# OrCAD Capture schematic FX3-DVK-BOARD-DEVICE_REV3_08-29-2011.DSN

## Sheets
1 PAGE07 : CLOCK SIGNALS: size B; title: FX3 DVK DEVICE BOARD; rev: 3.0; note: 630-60013-01 REV03
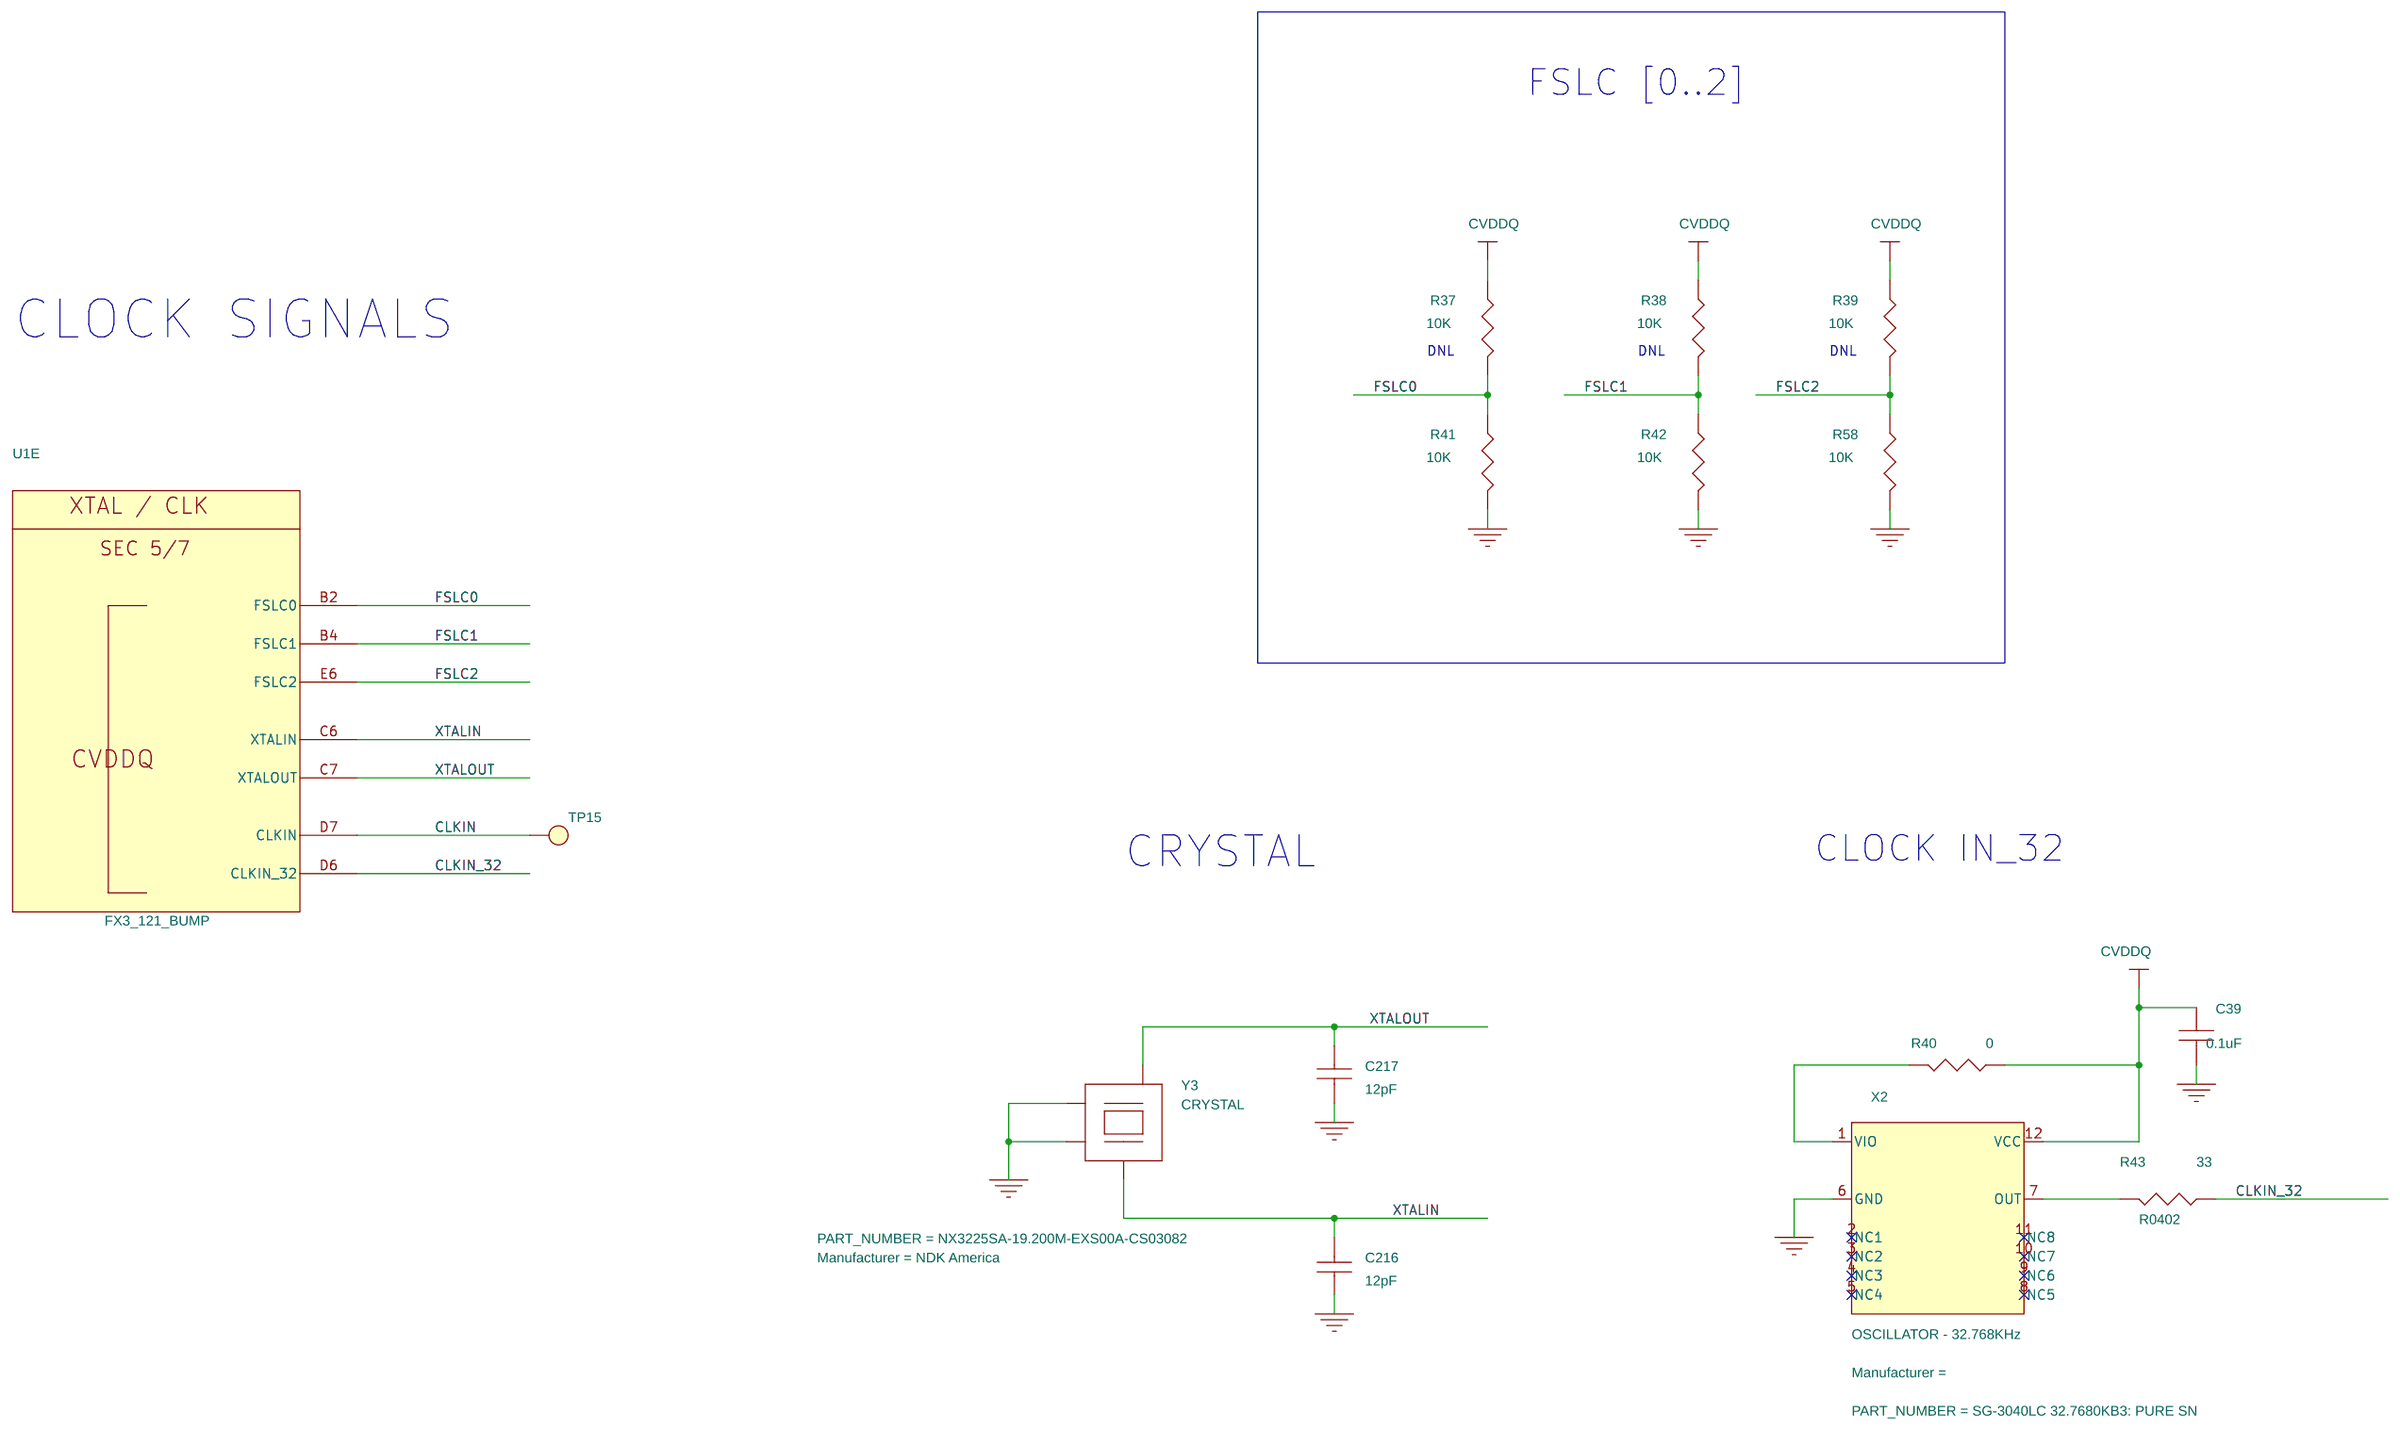
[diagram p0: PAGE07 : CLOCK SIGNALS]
2 PAGE14 : Power LED: size B
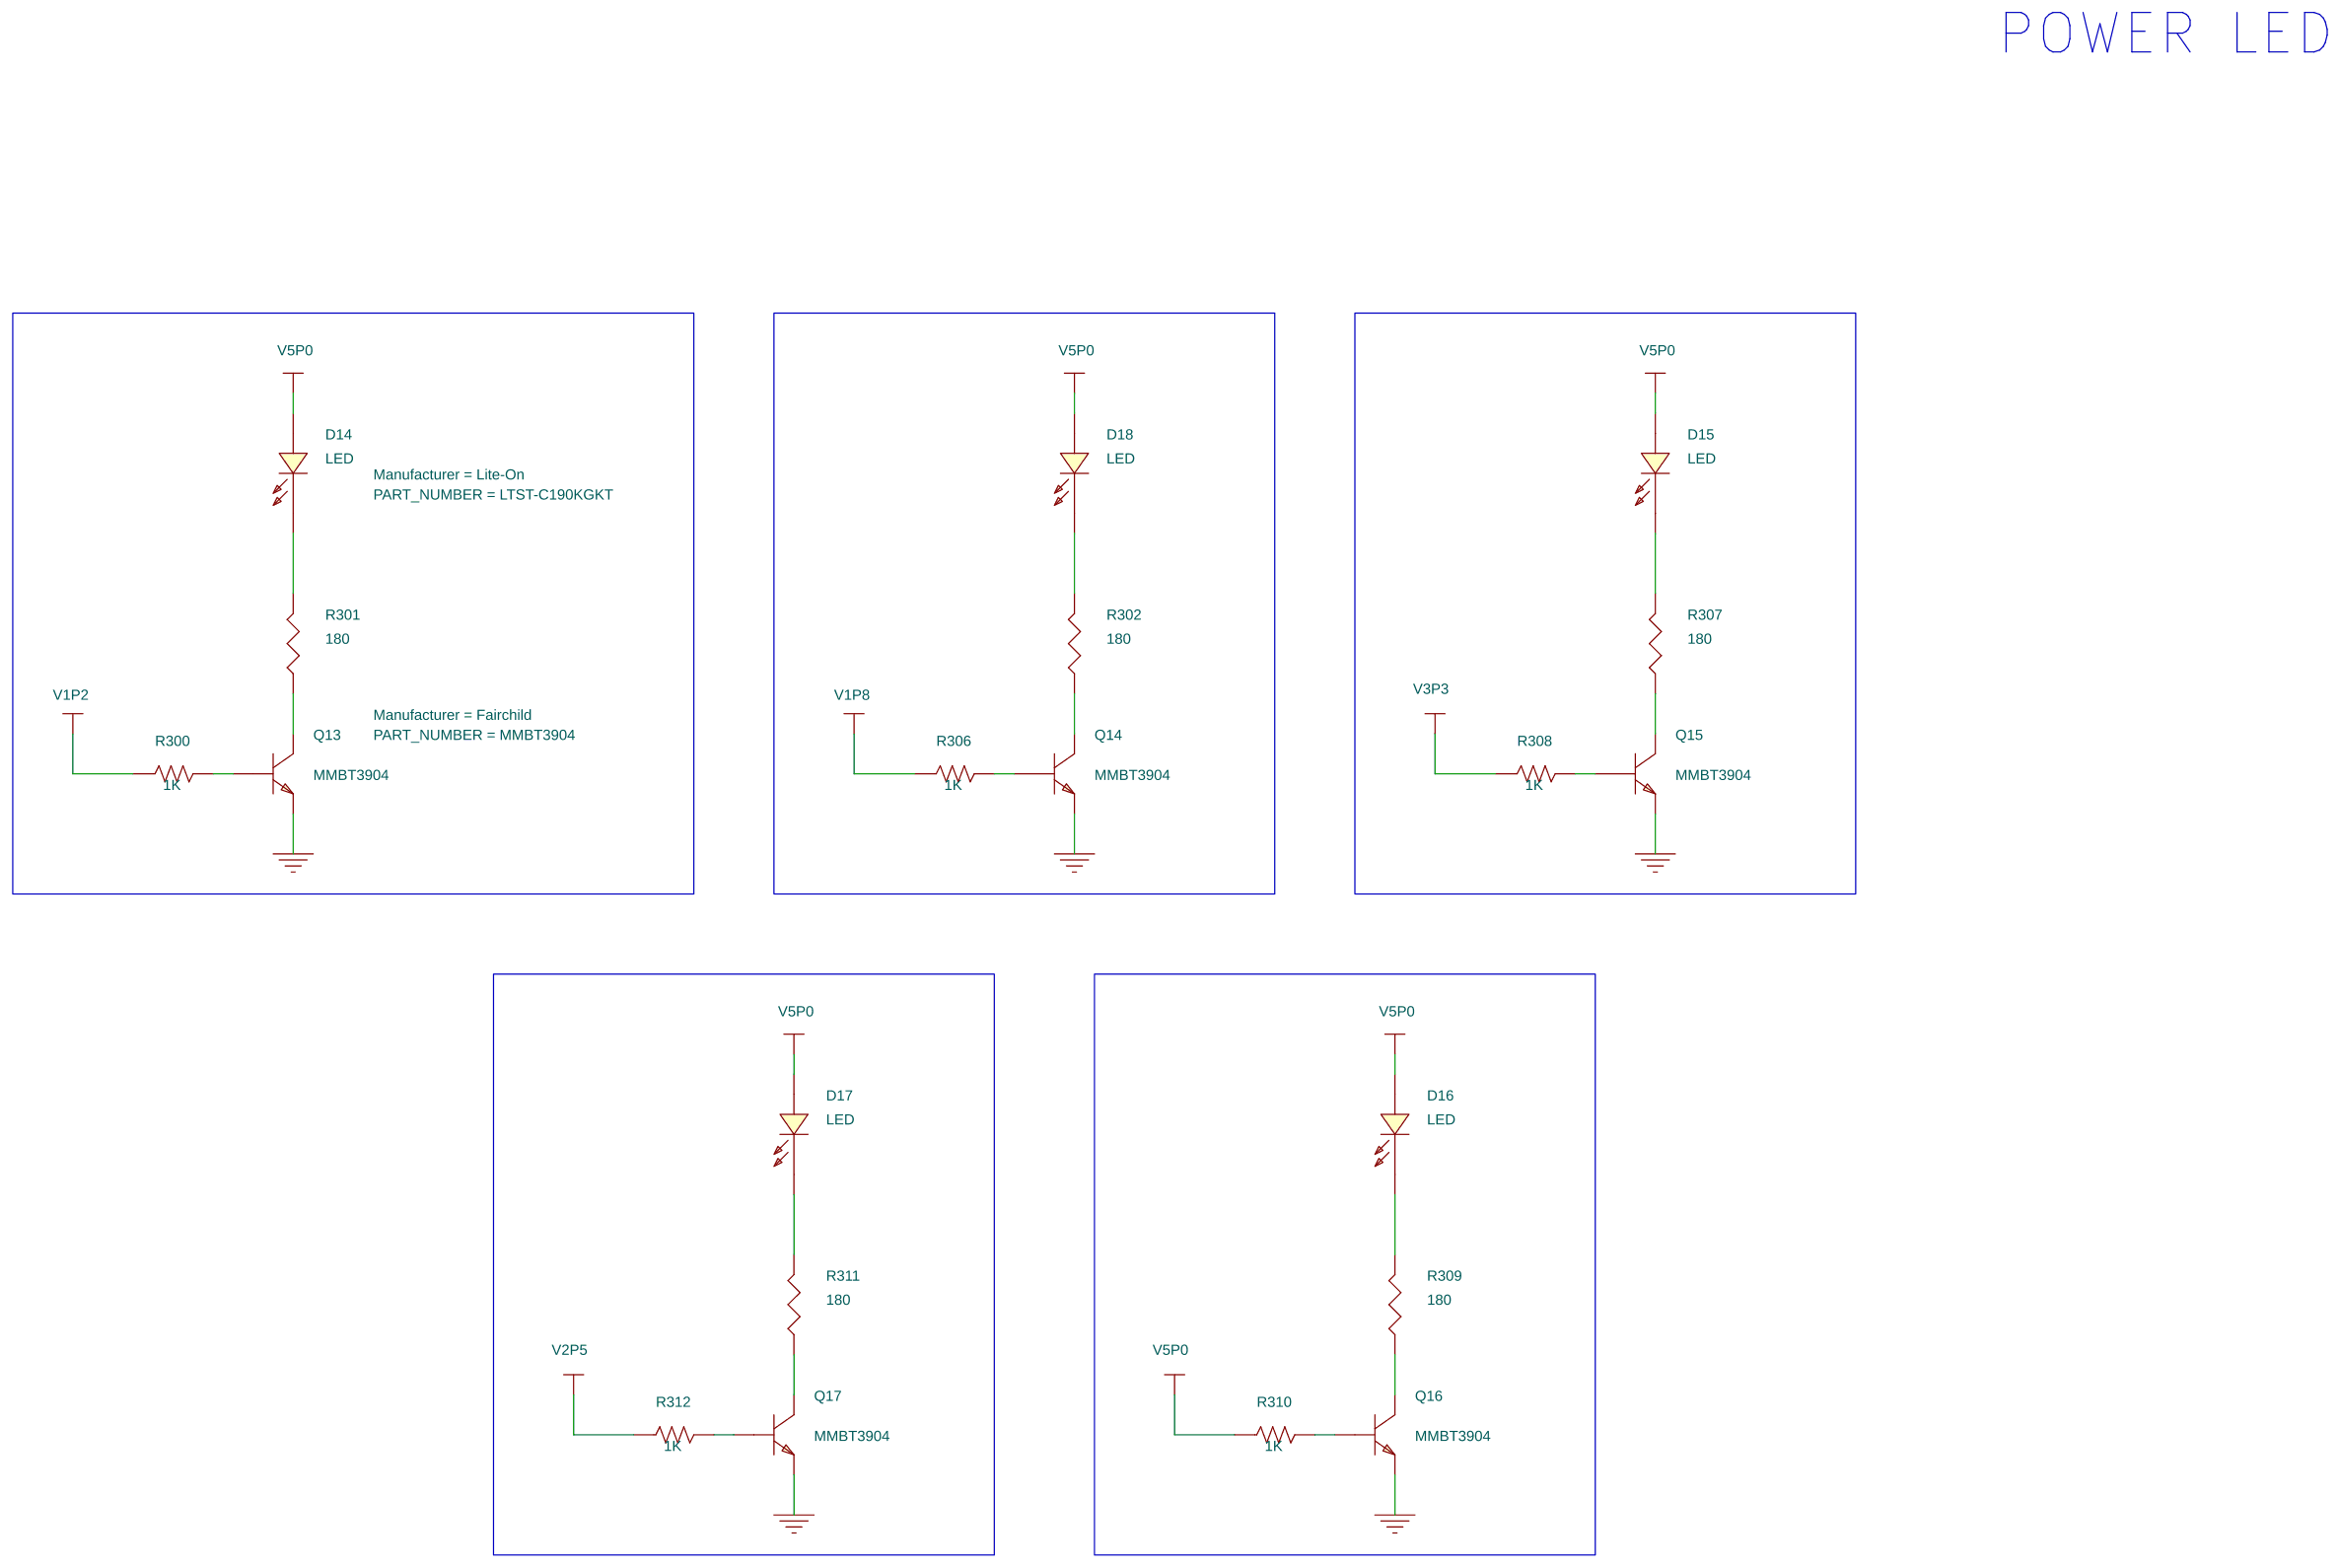
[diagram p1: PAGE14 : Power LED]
3 PAGE10 : FX3 POWER: size B
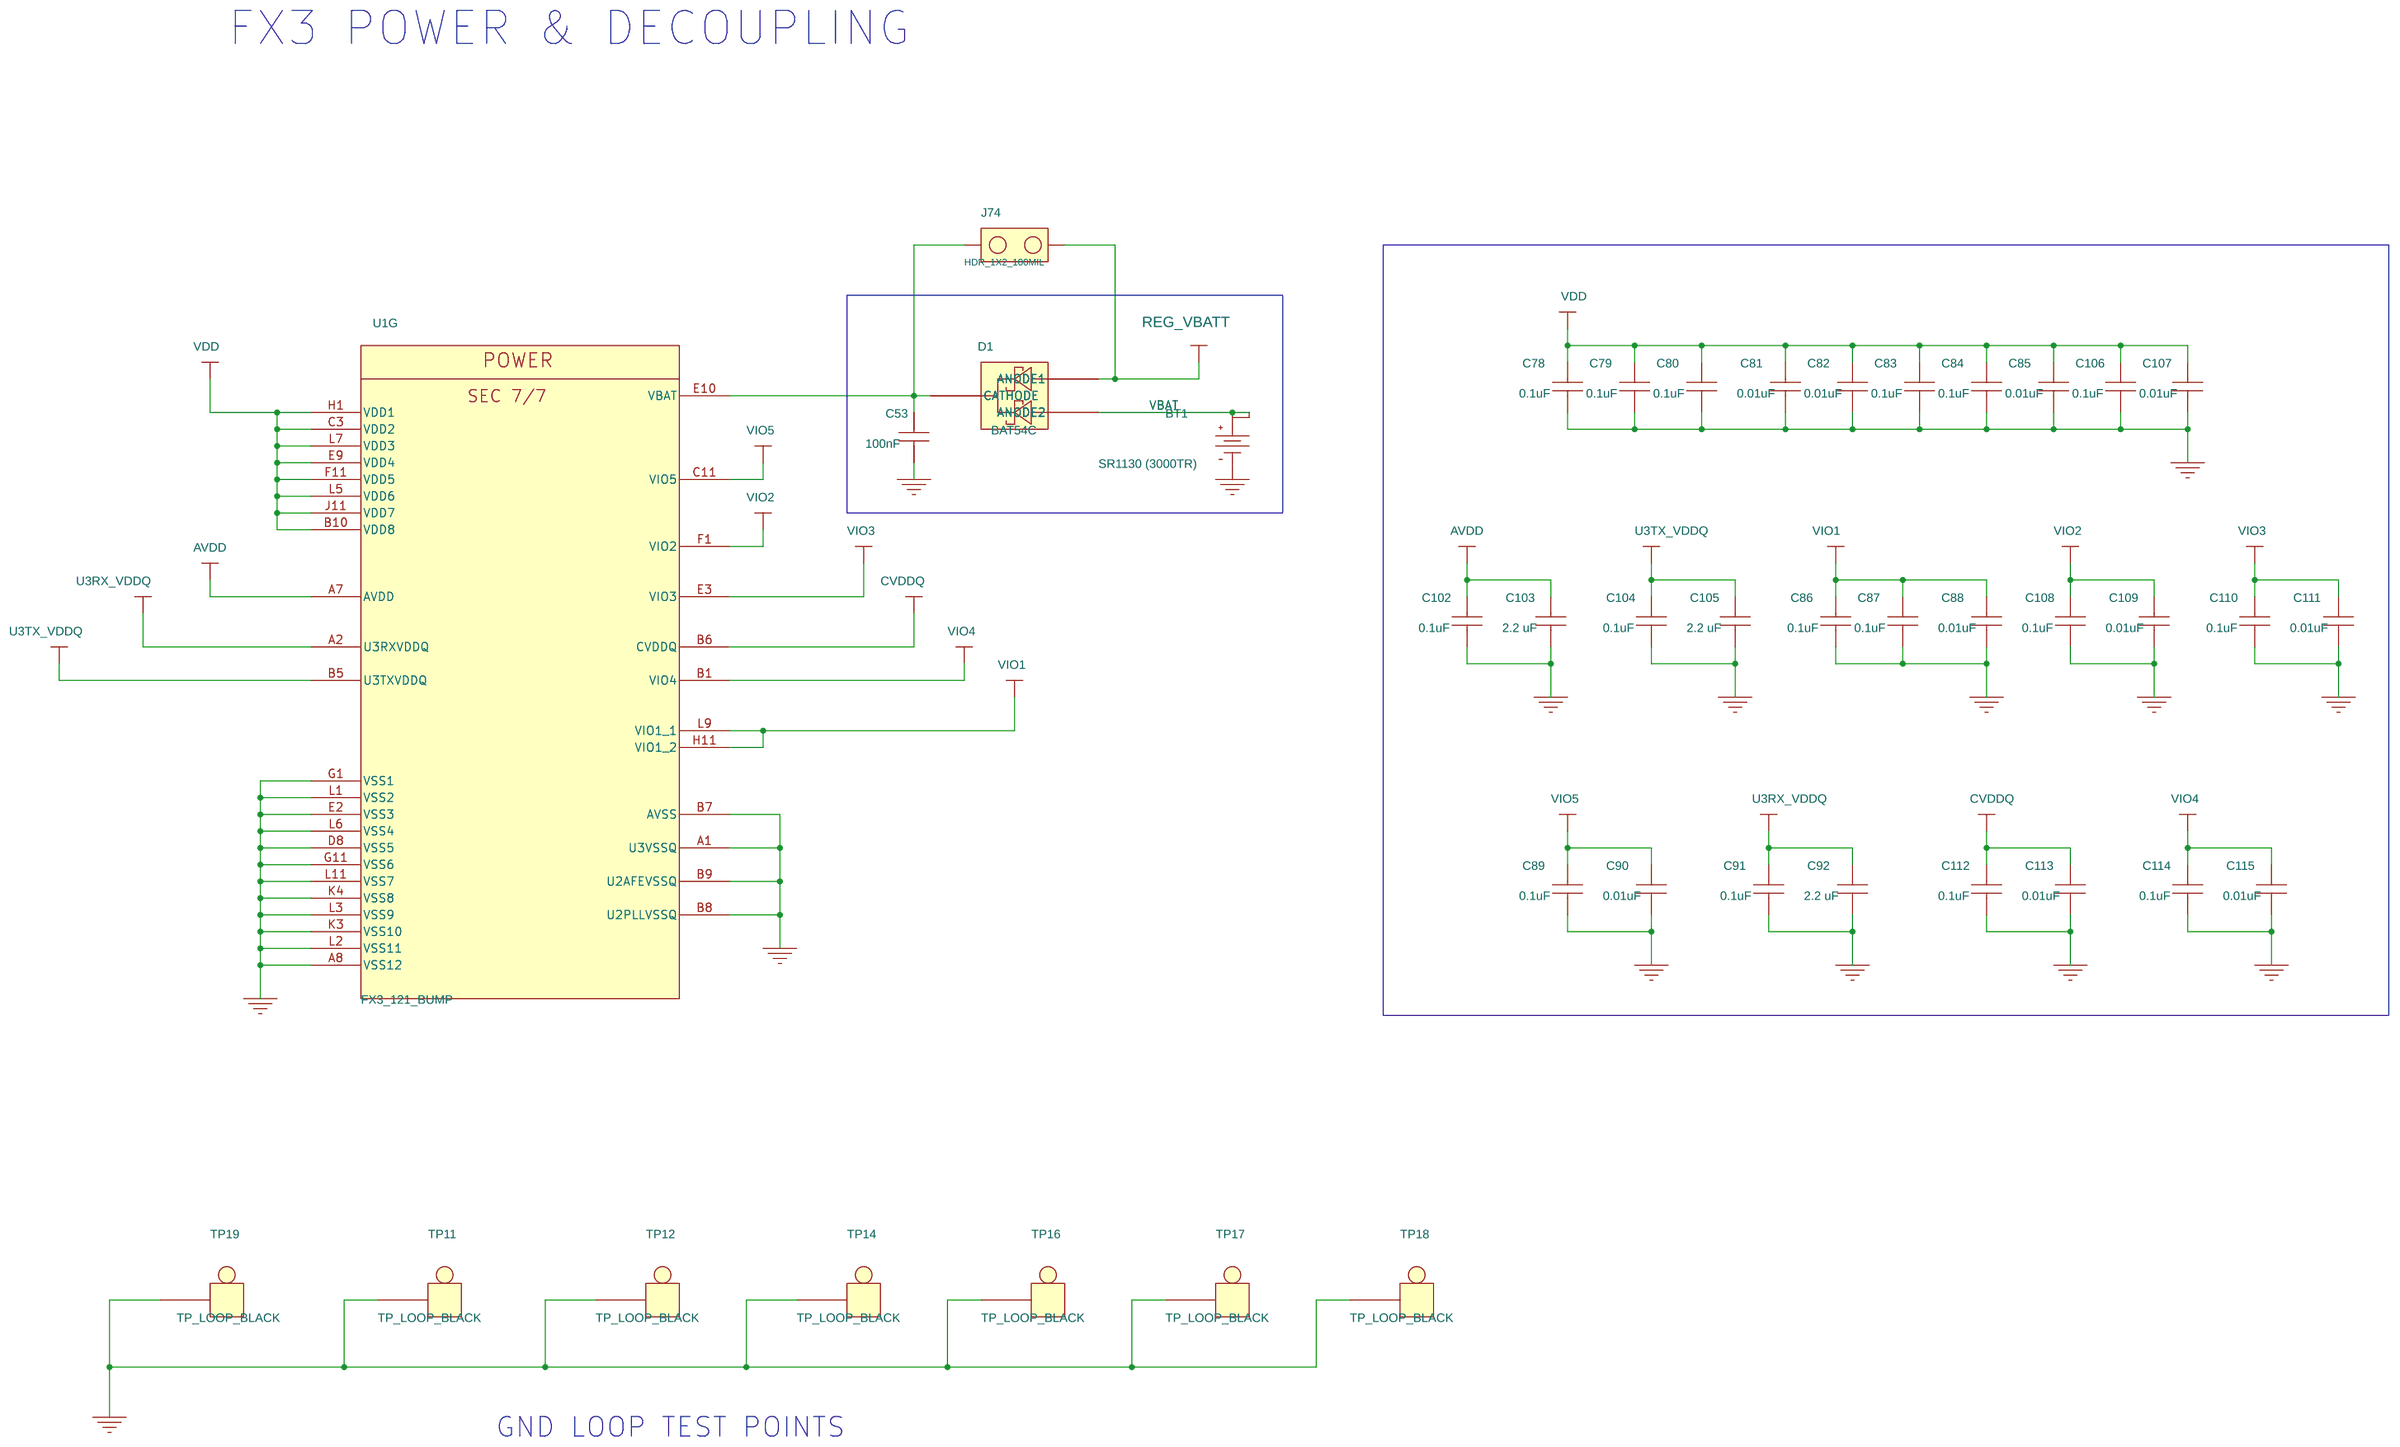
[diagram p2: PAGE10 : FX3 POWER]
4 PAGE01 : INDEX PAGE: rev: 2.0; note: 630-60013-01 REV02
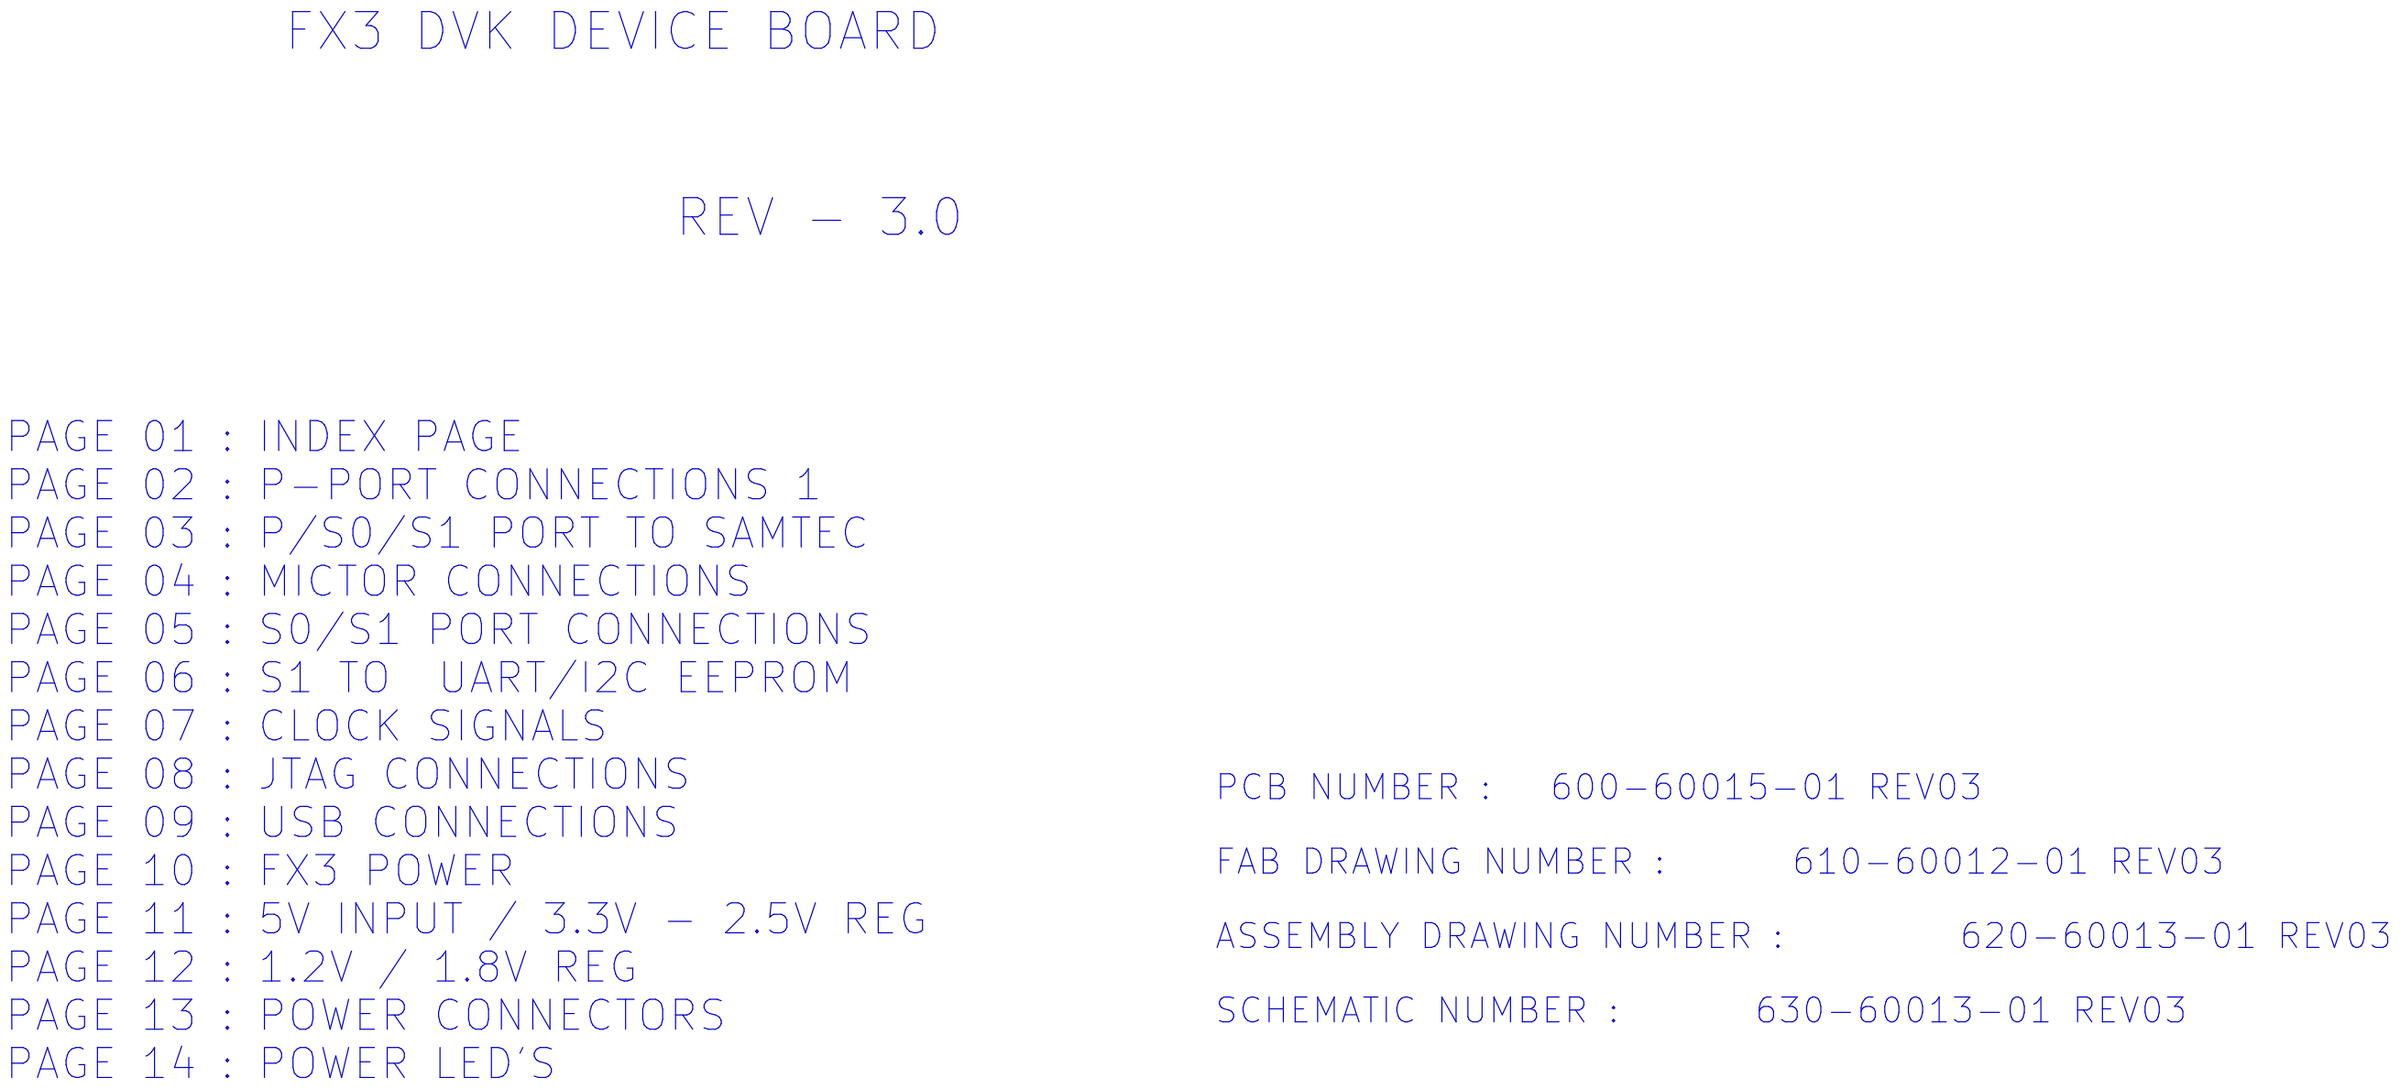
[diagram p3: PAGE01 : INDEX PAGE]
5 PAGE04 : MICTOR CONNECTIONS: size B
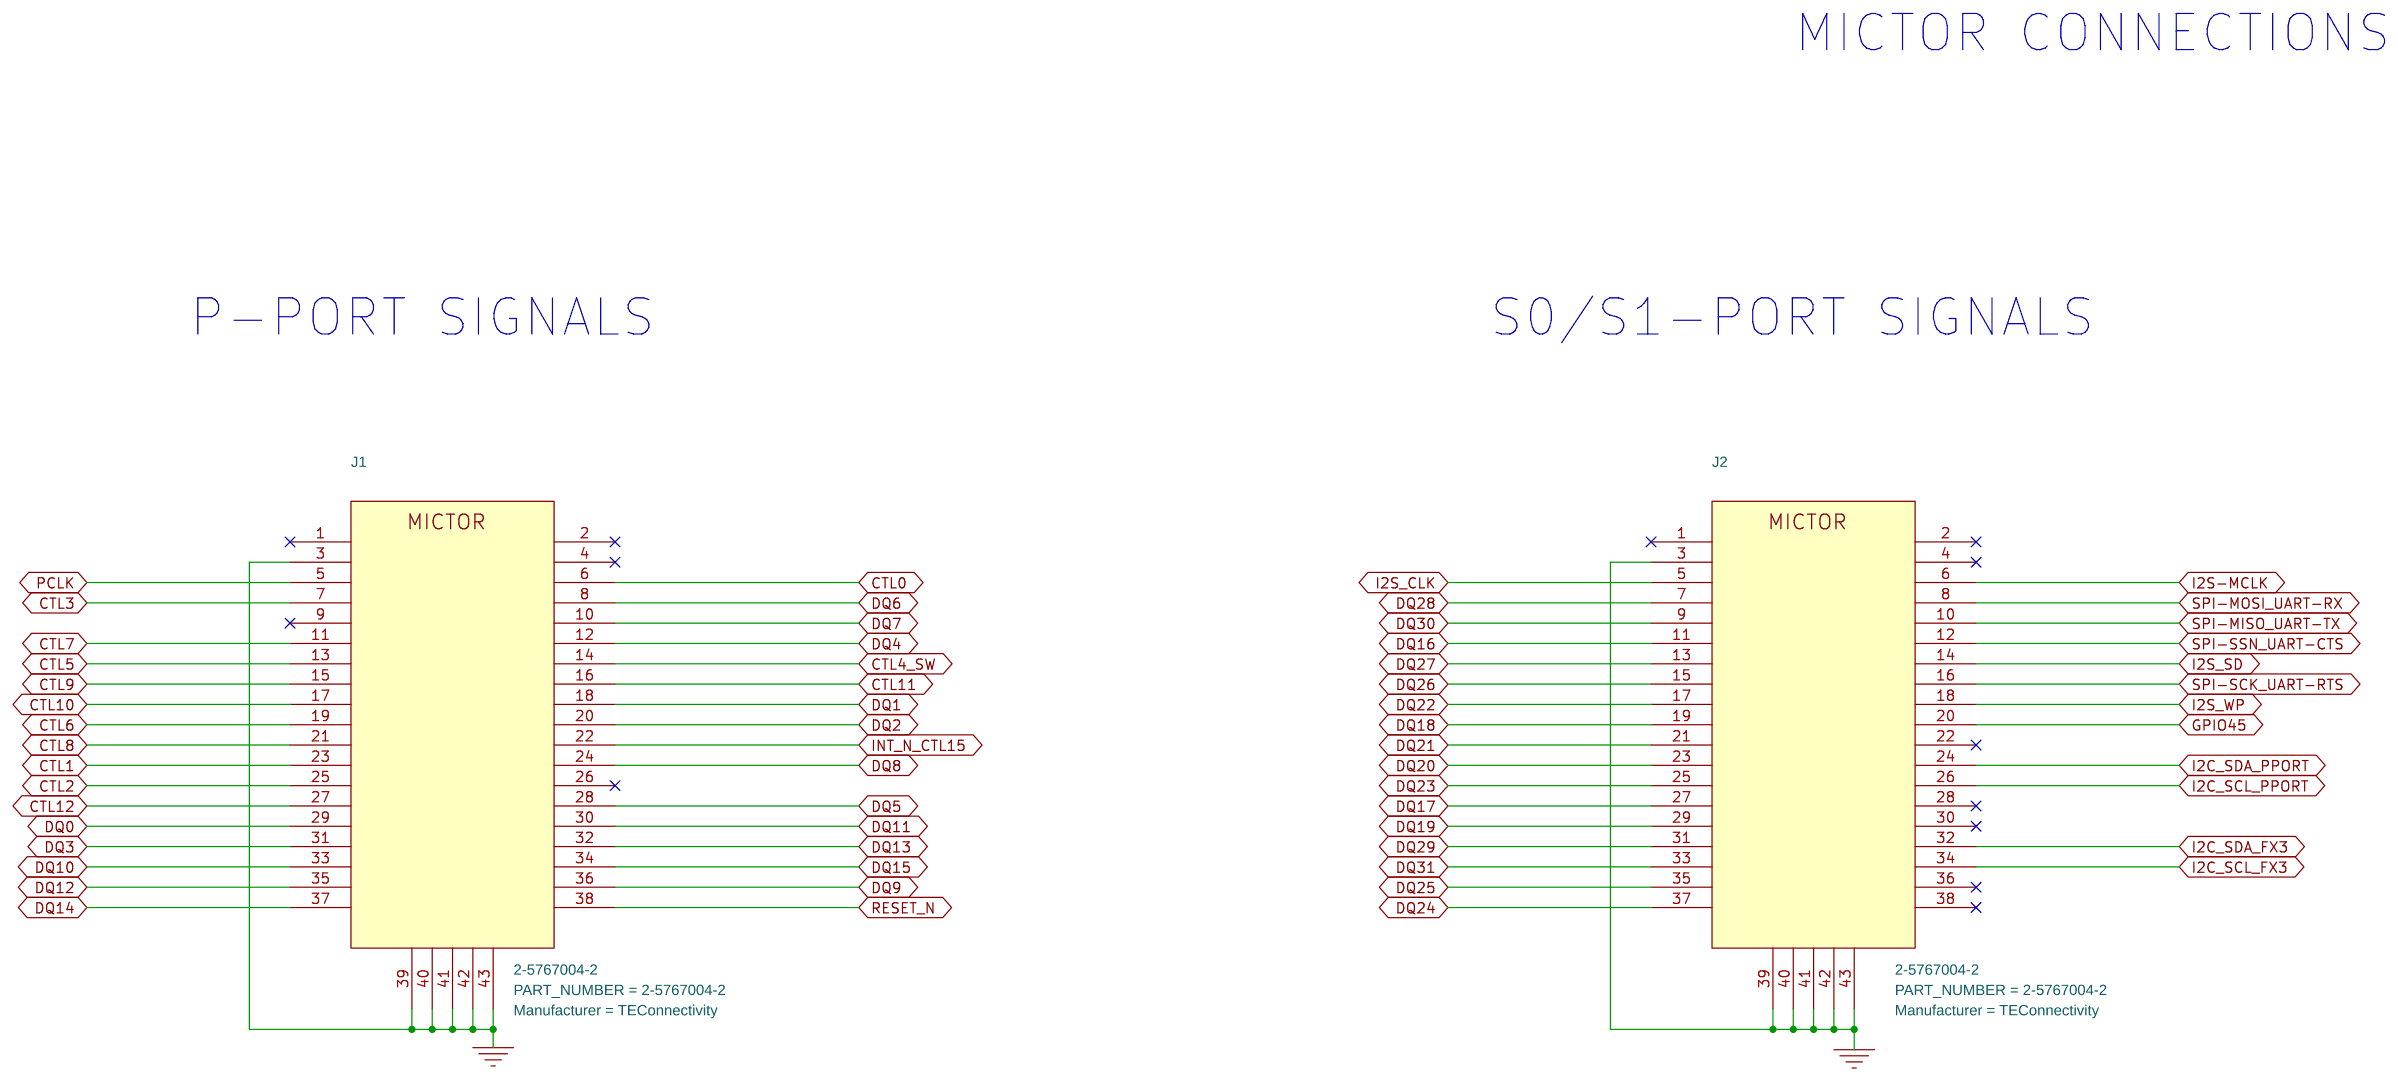
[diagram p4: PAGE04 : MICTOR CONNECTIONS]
6 PAGE09 : USB CONNECTIONS: size B
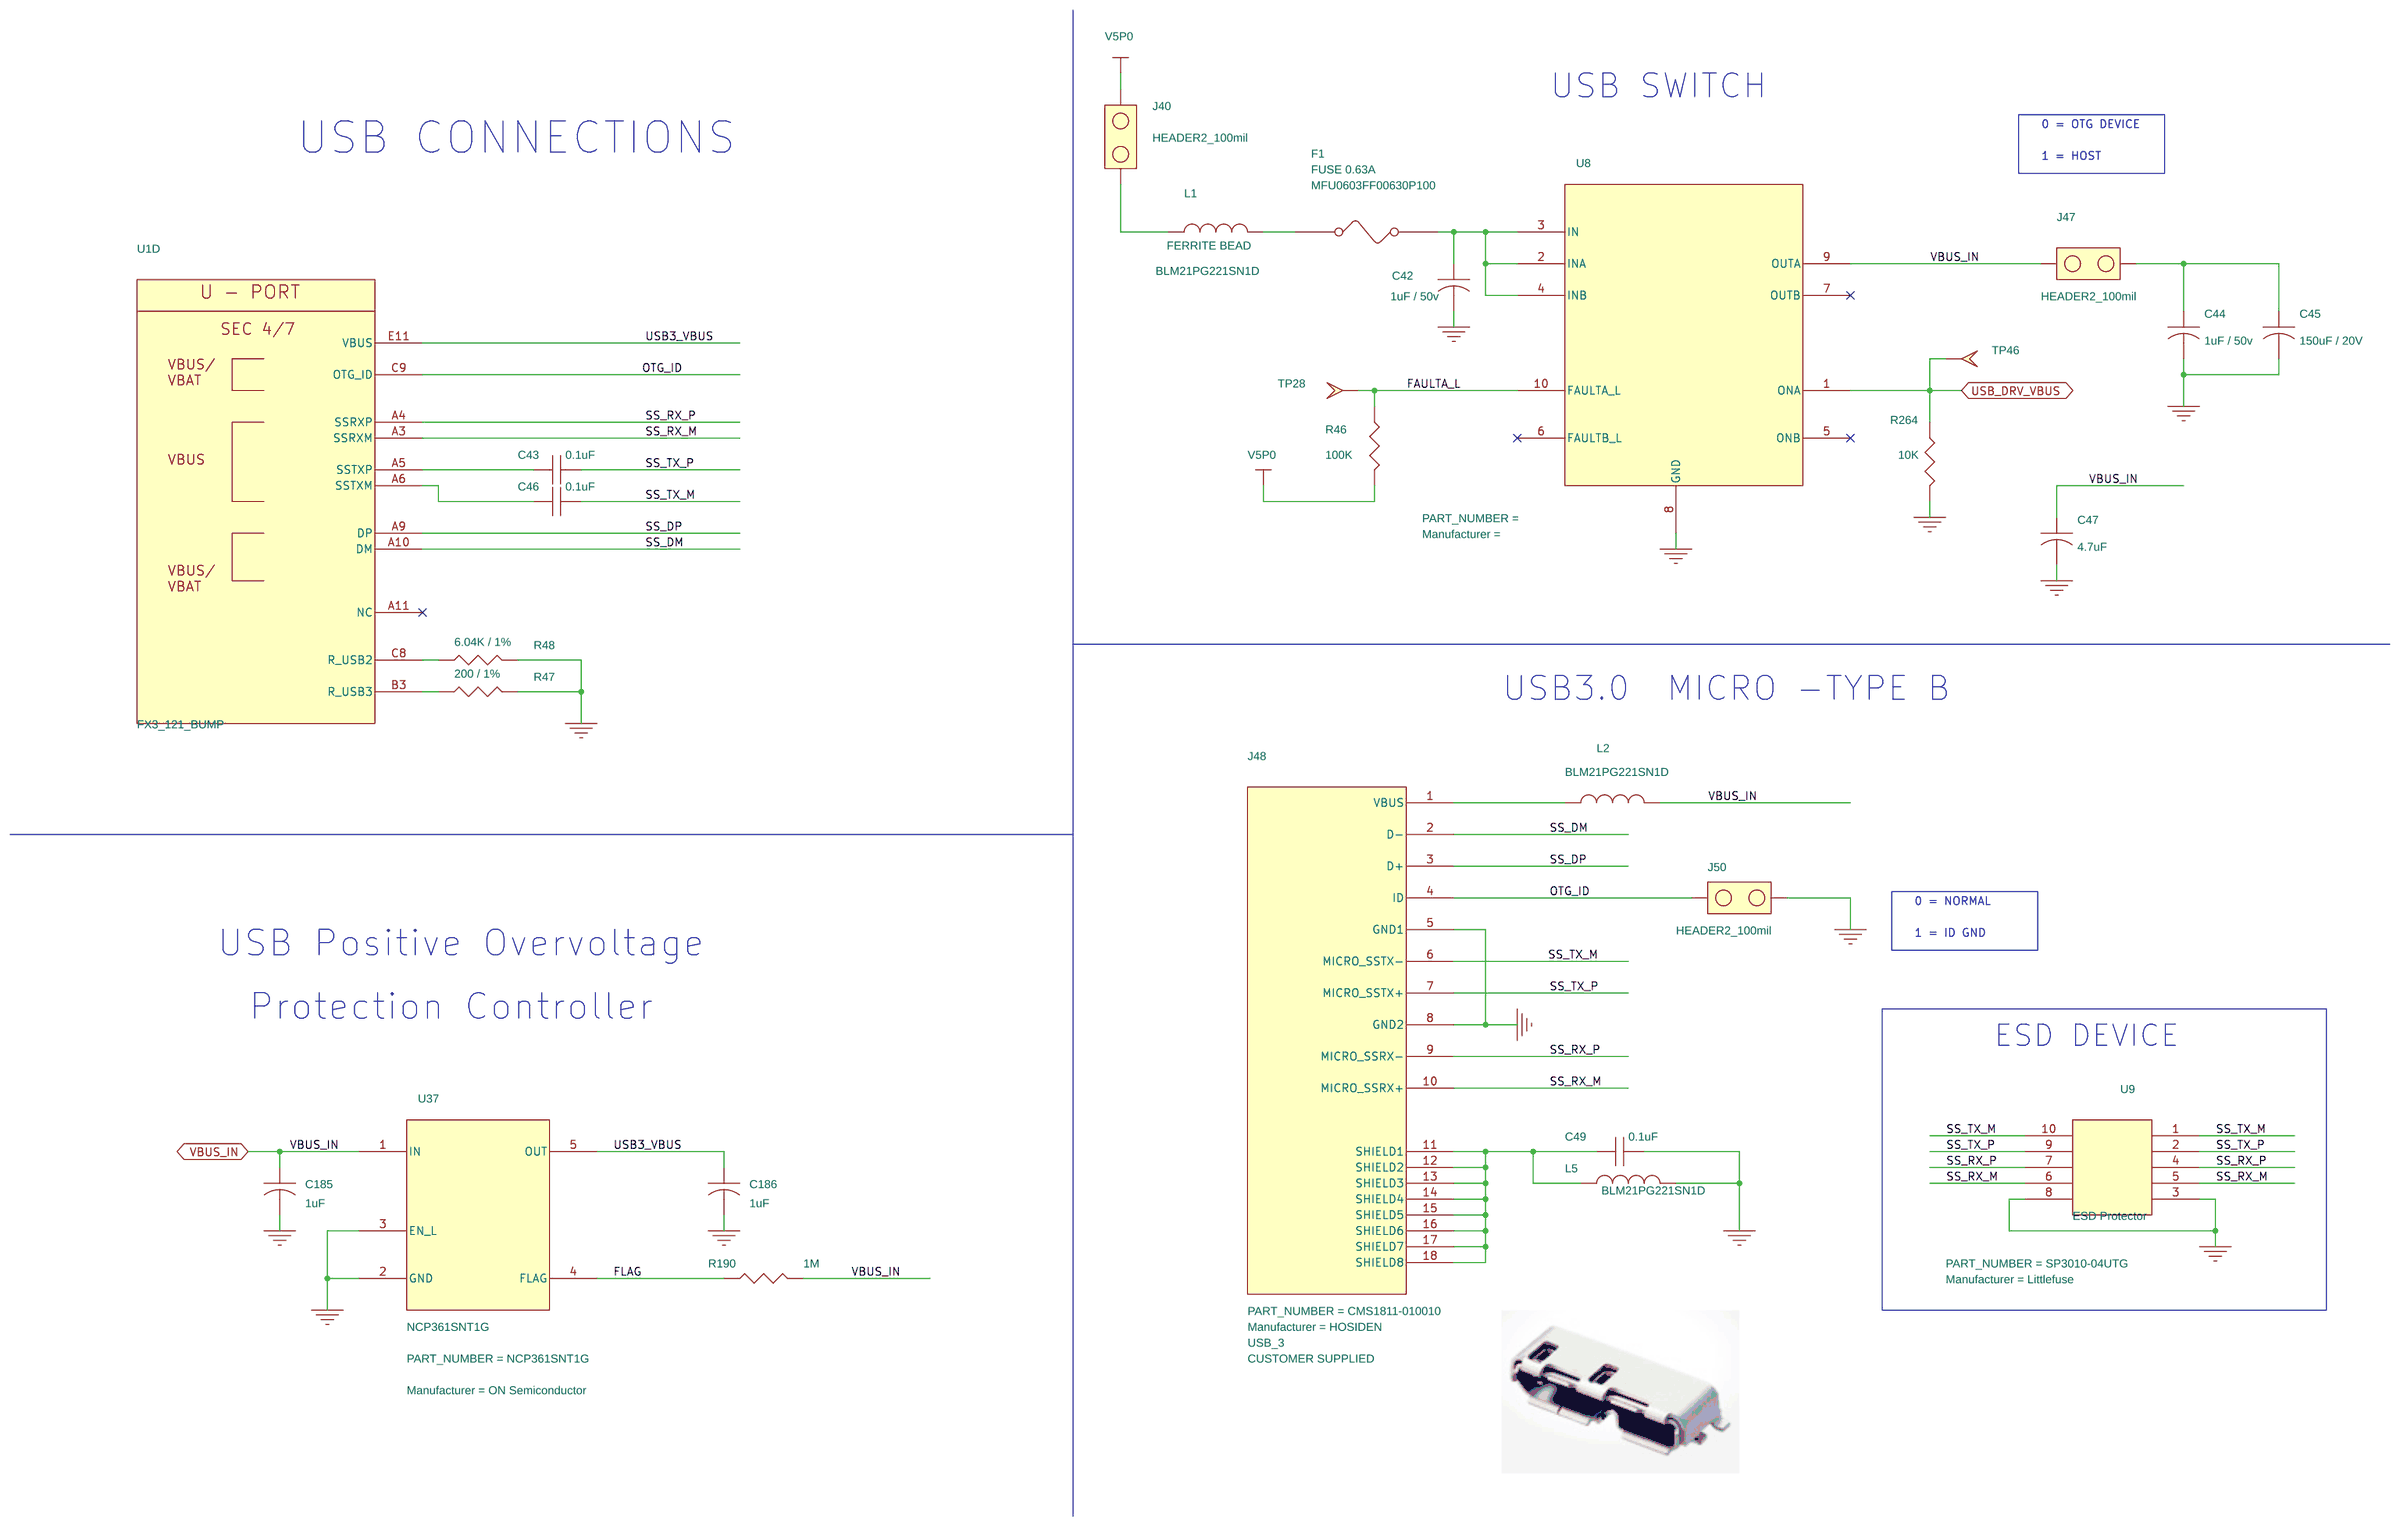
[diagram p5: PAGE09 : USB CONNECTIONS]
7 PAGE13 : POWER HEADERS: size B
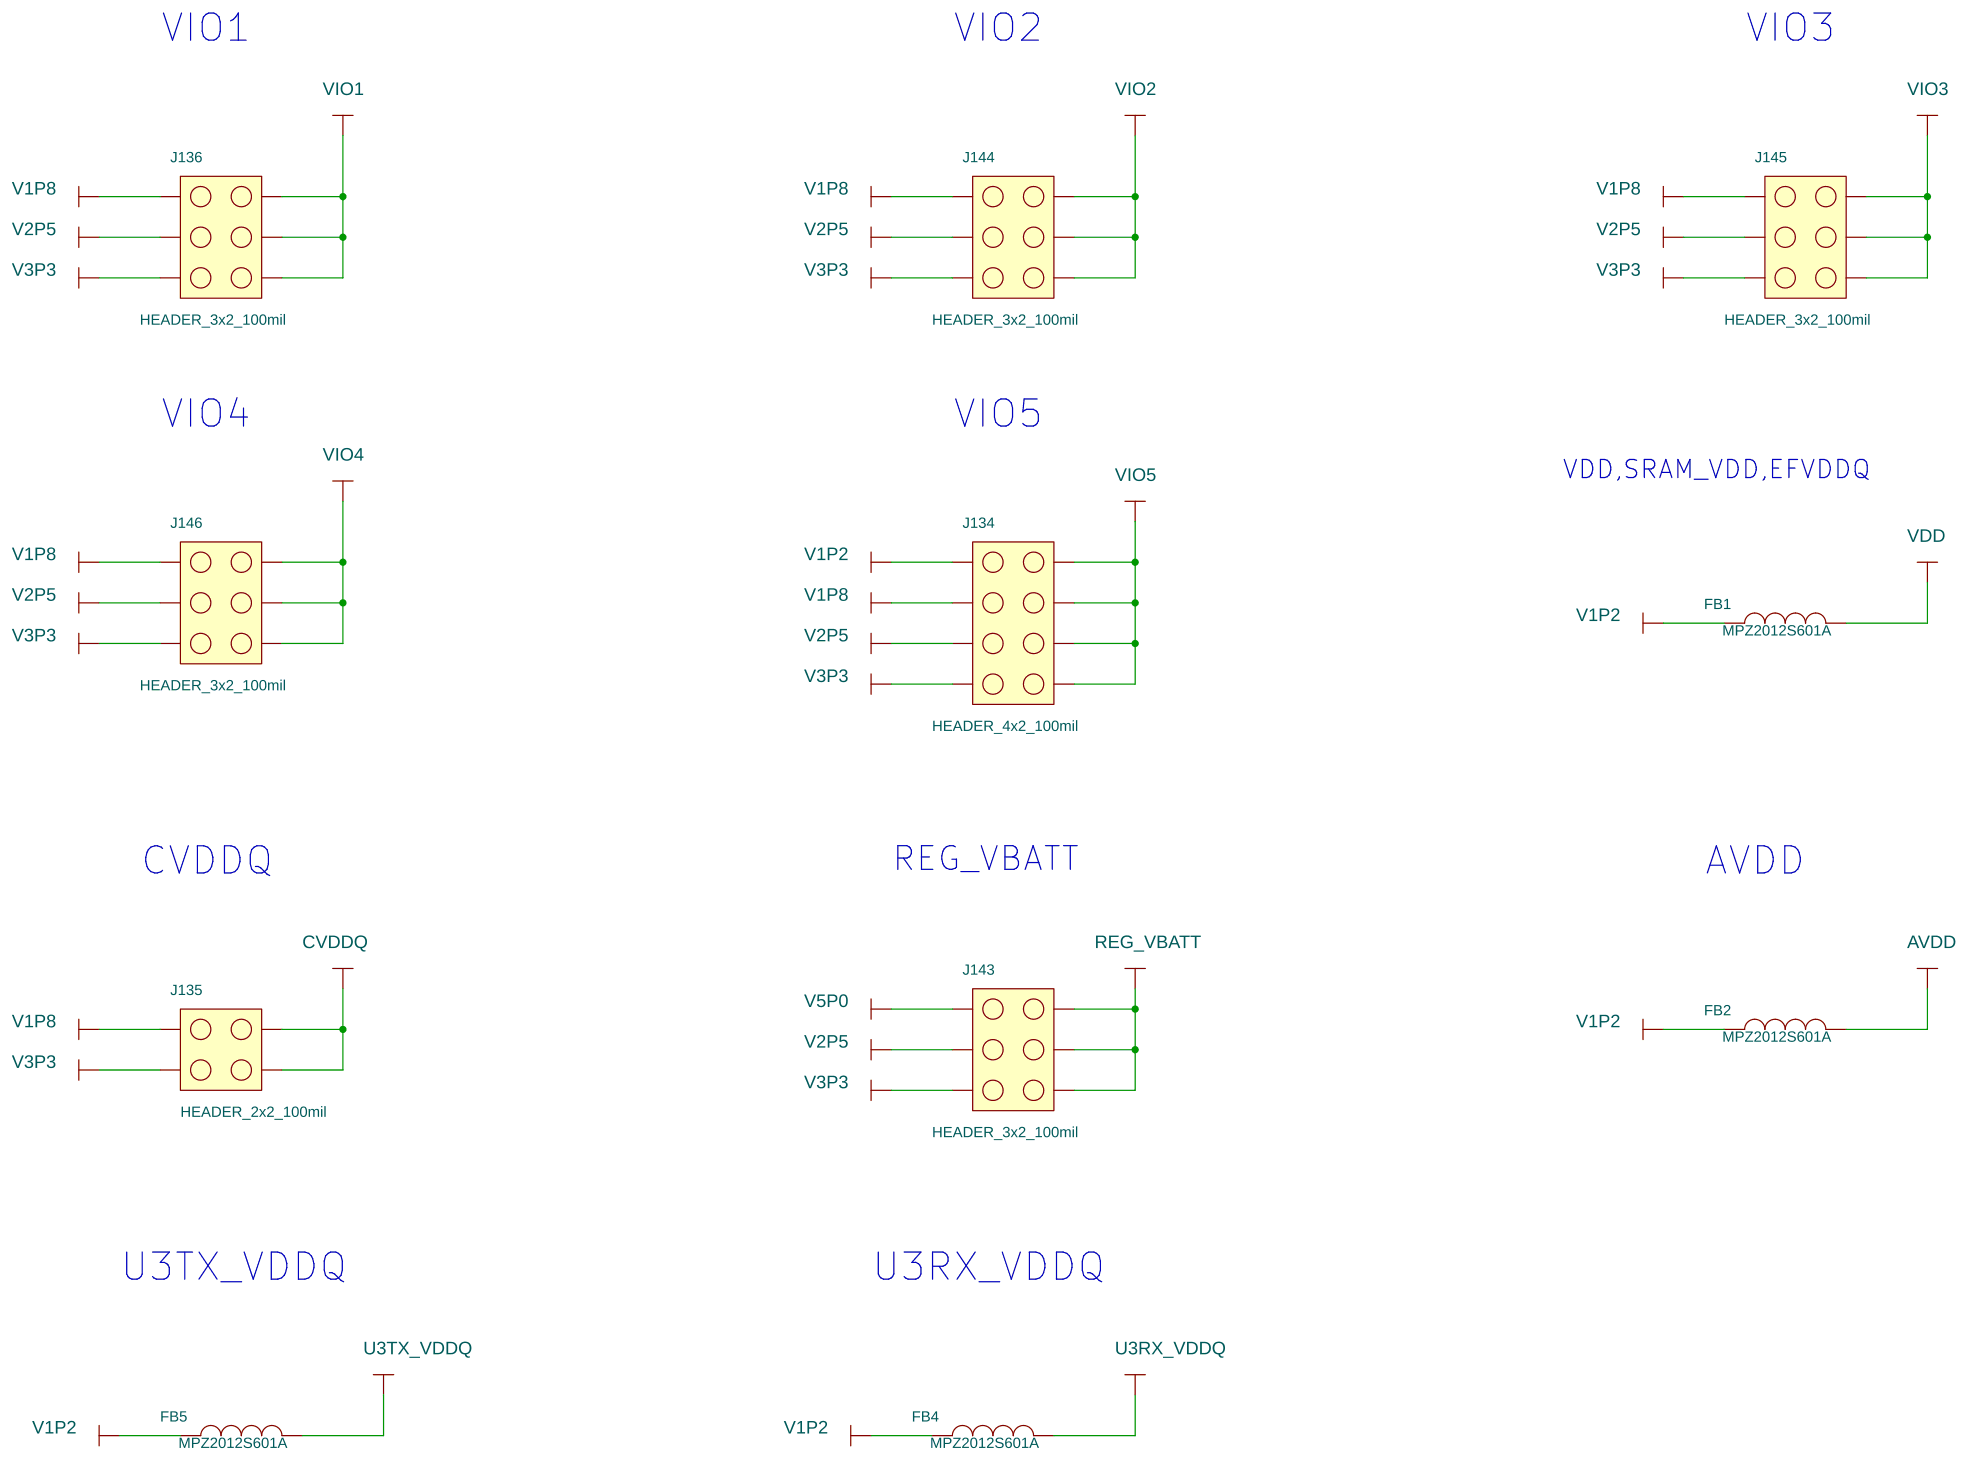
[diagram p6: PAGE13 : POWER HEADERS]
8 PAGE08 : JTAG CONNECTIONS: size B
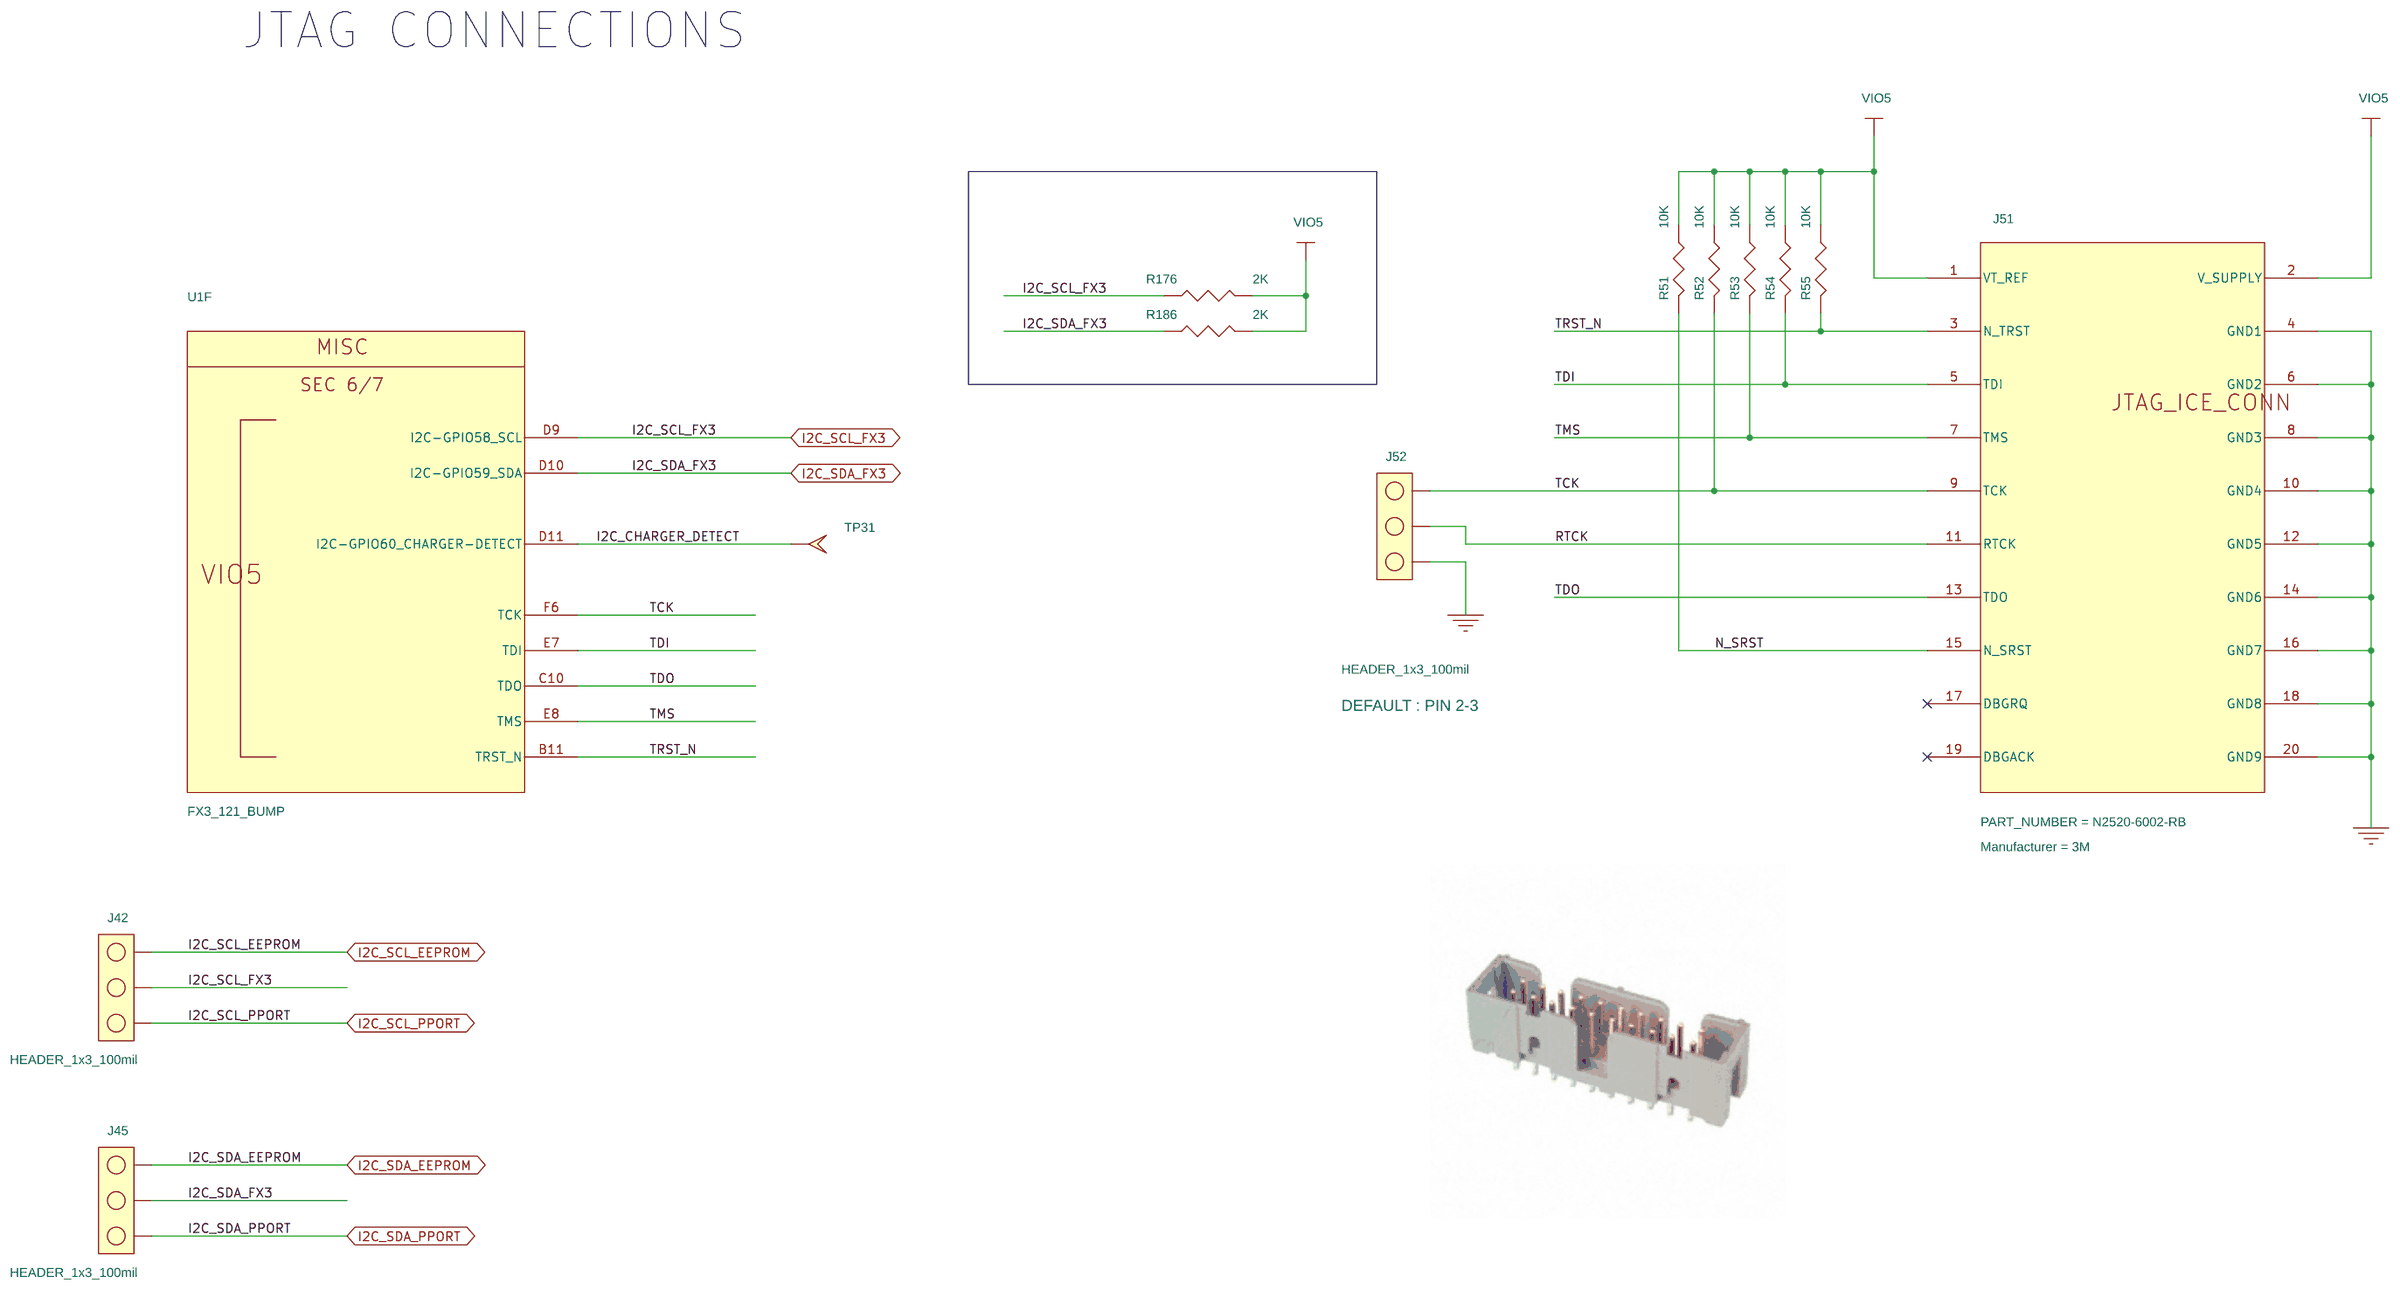
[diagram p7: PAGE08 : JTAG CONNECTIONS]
9 PAGE03 : P/S0/S1 PORT TO SAMTEC: size B; rev: 2.0; note: 630-60013-01 REV02
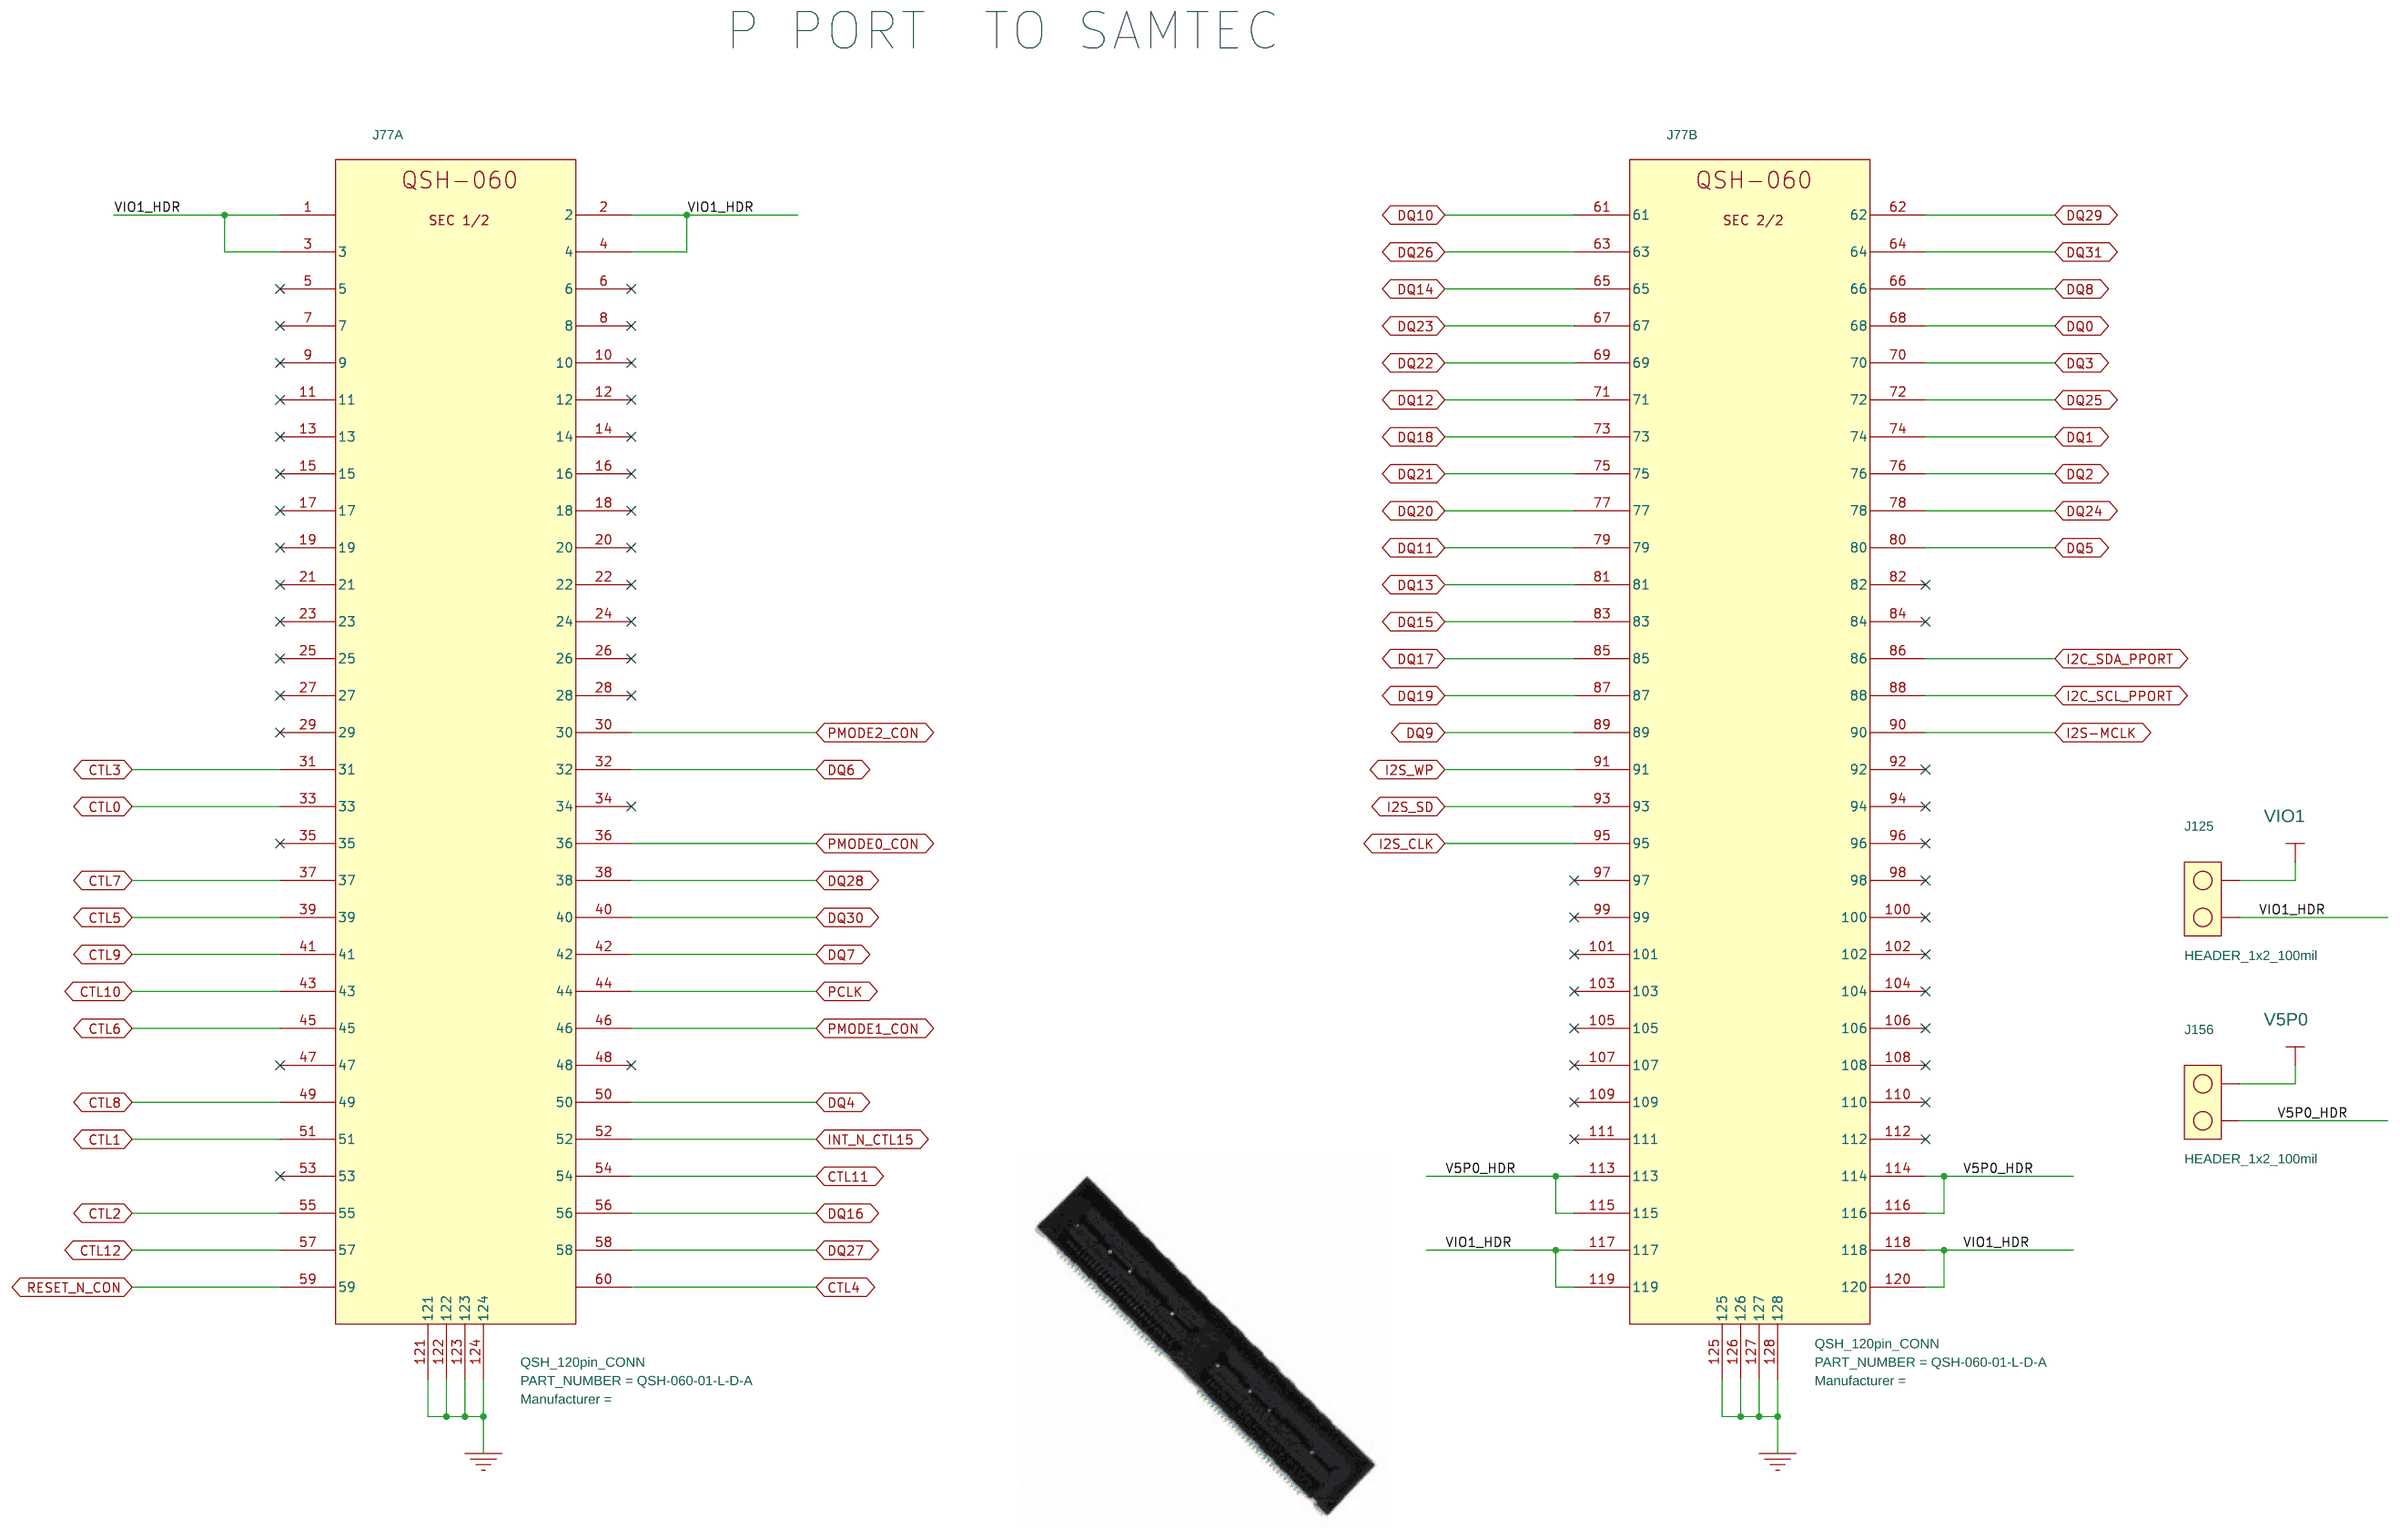
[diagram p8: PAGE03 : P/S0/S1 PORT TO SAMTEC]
10 PAGE02 : P-PORT CONNECTIONS 1: size B; rev: 2.0; note: 630-60013-01 REV02
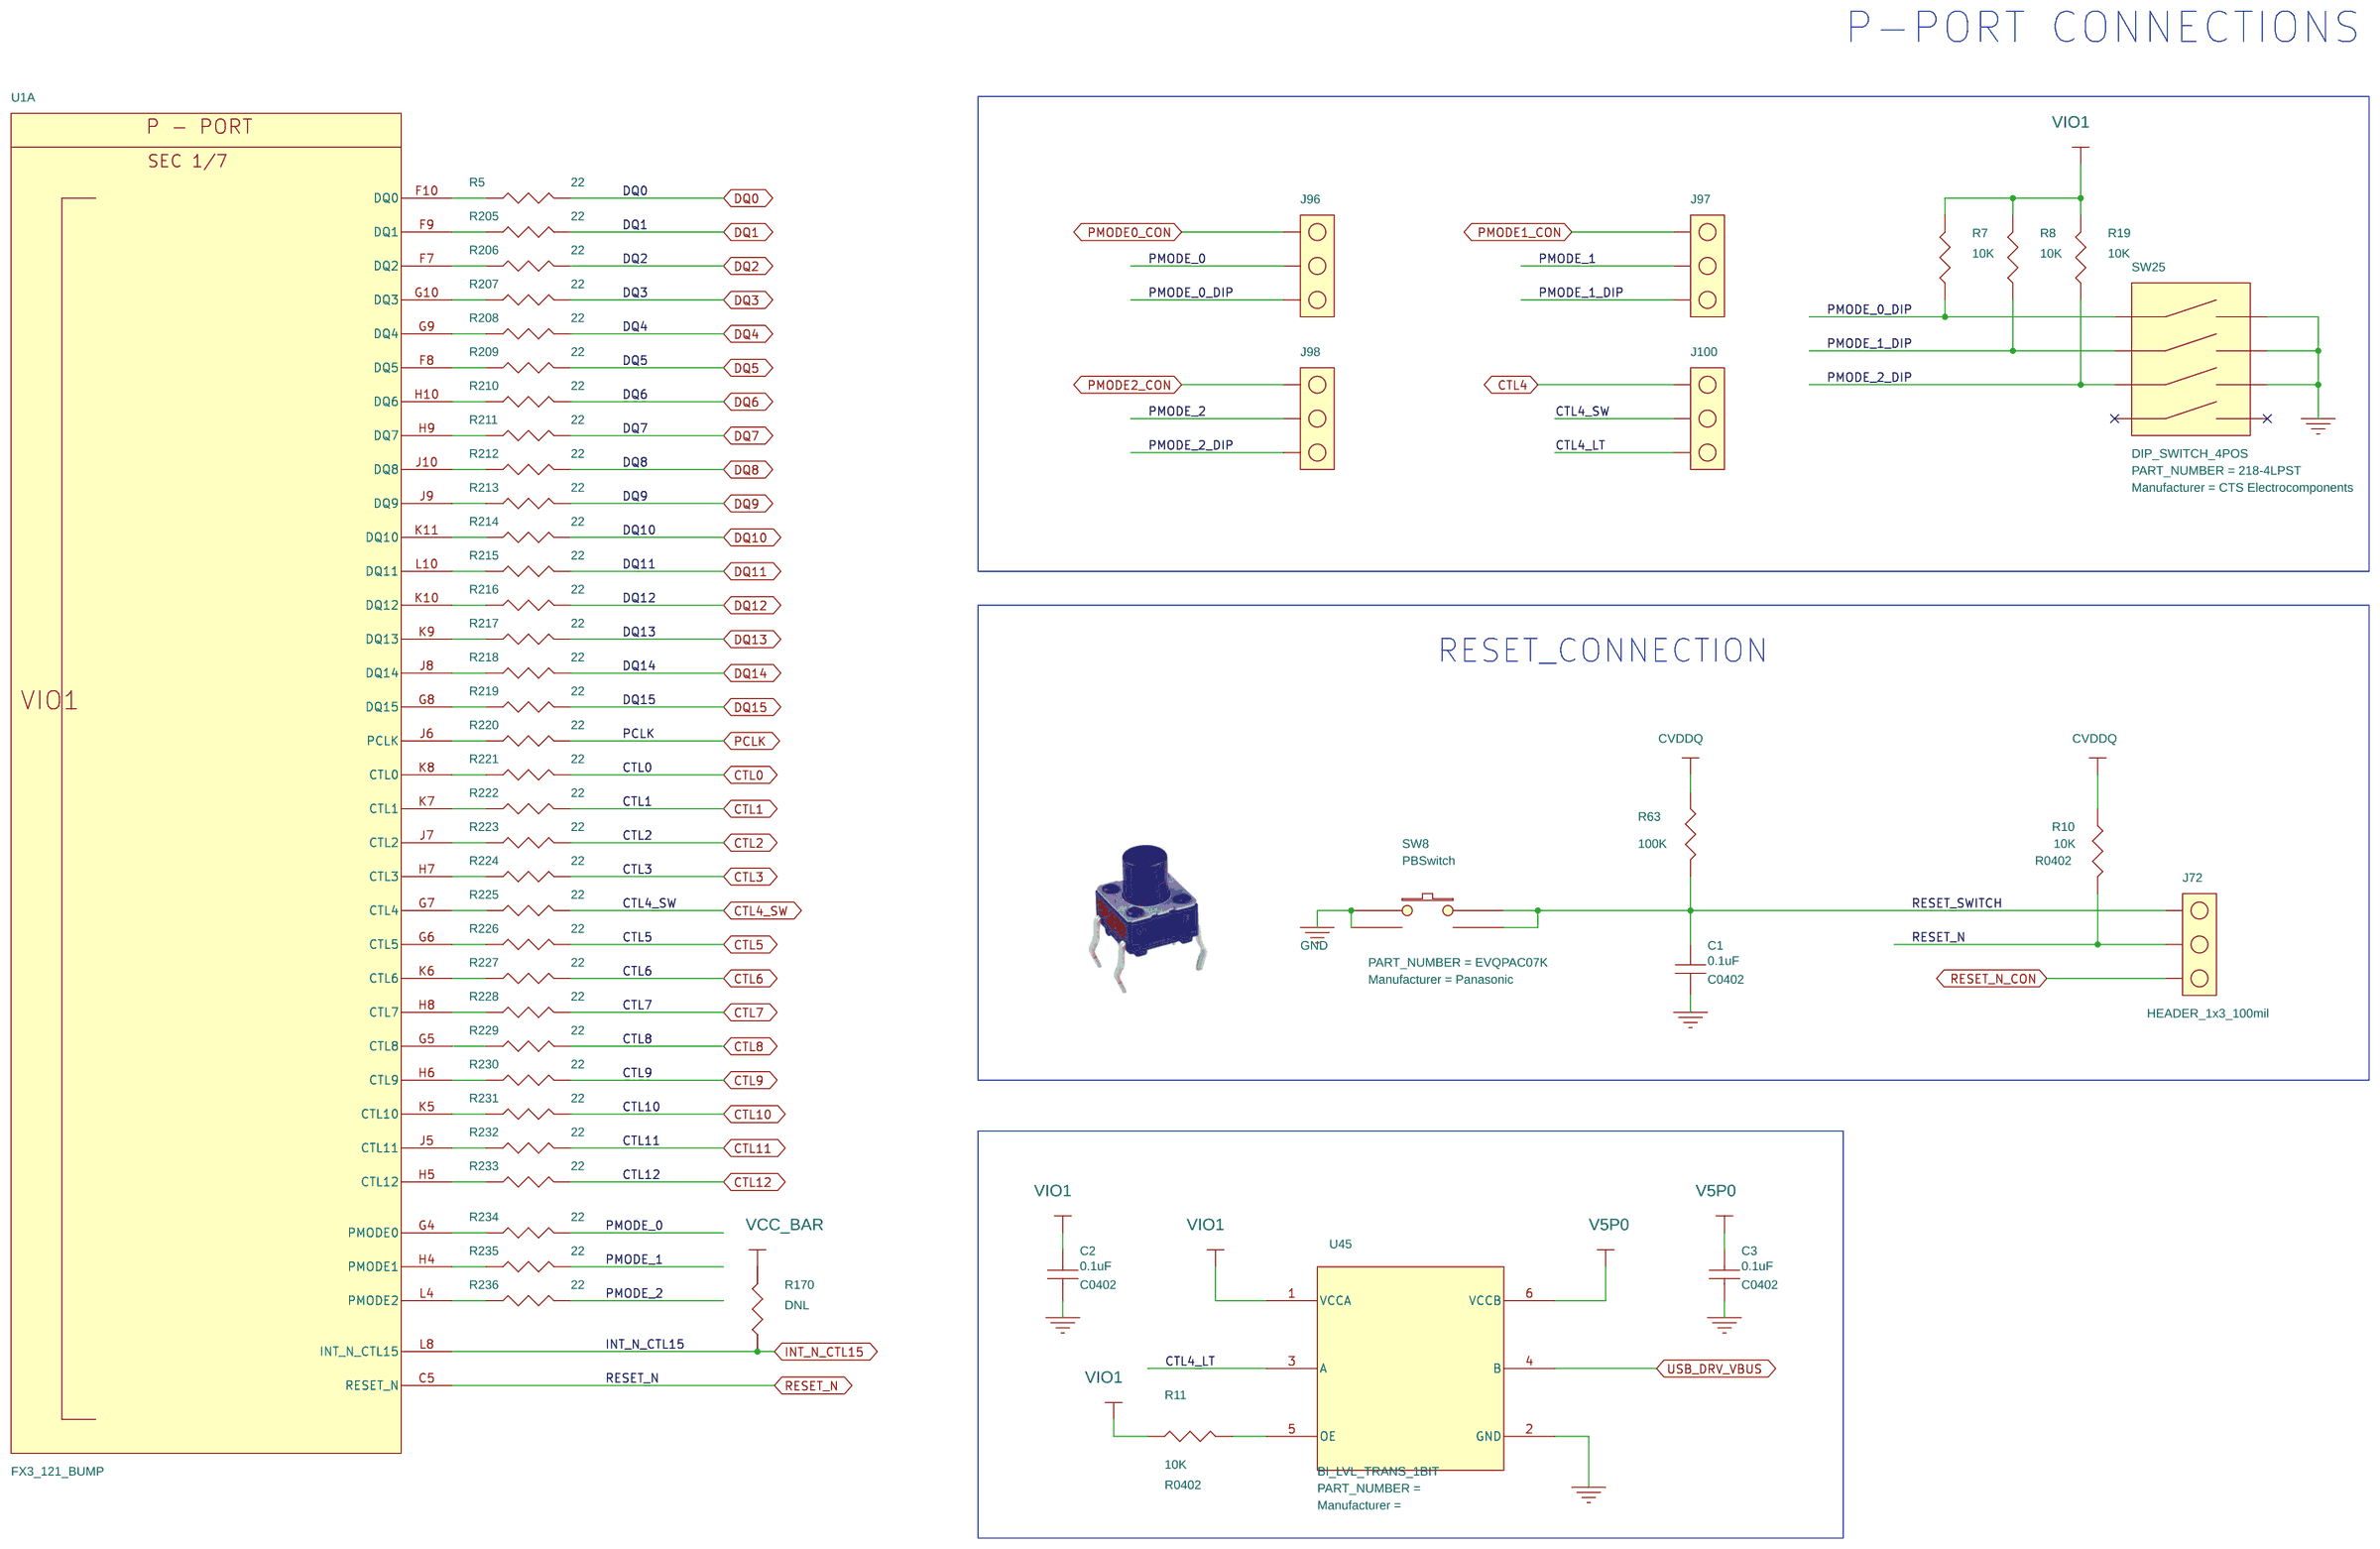
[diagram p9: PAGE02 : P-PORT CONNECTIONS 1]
11 PAGE06 : S1 TO  UART/I2C EEPROM: size B
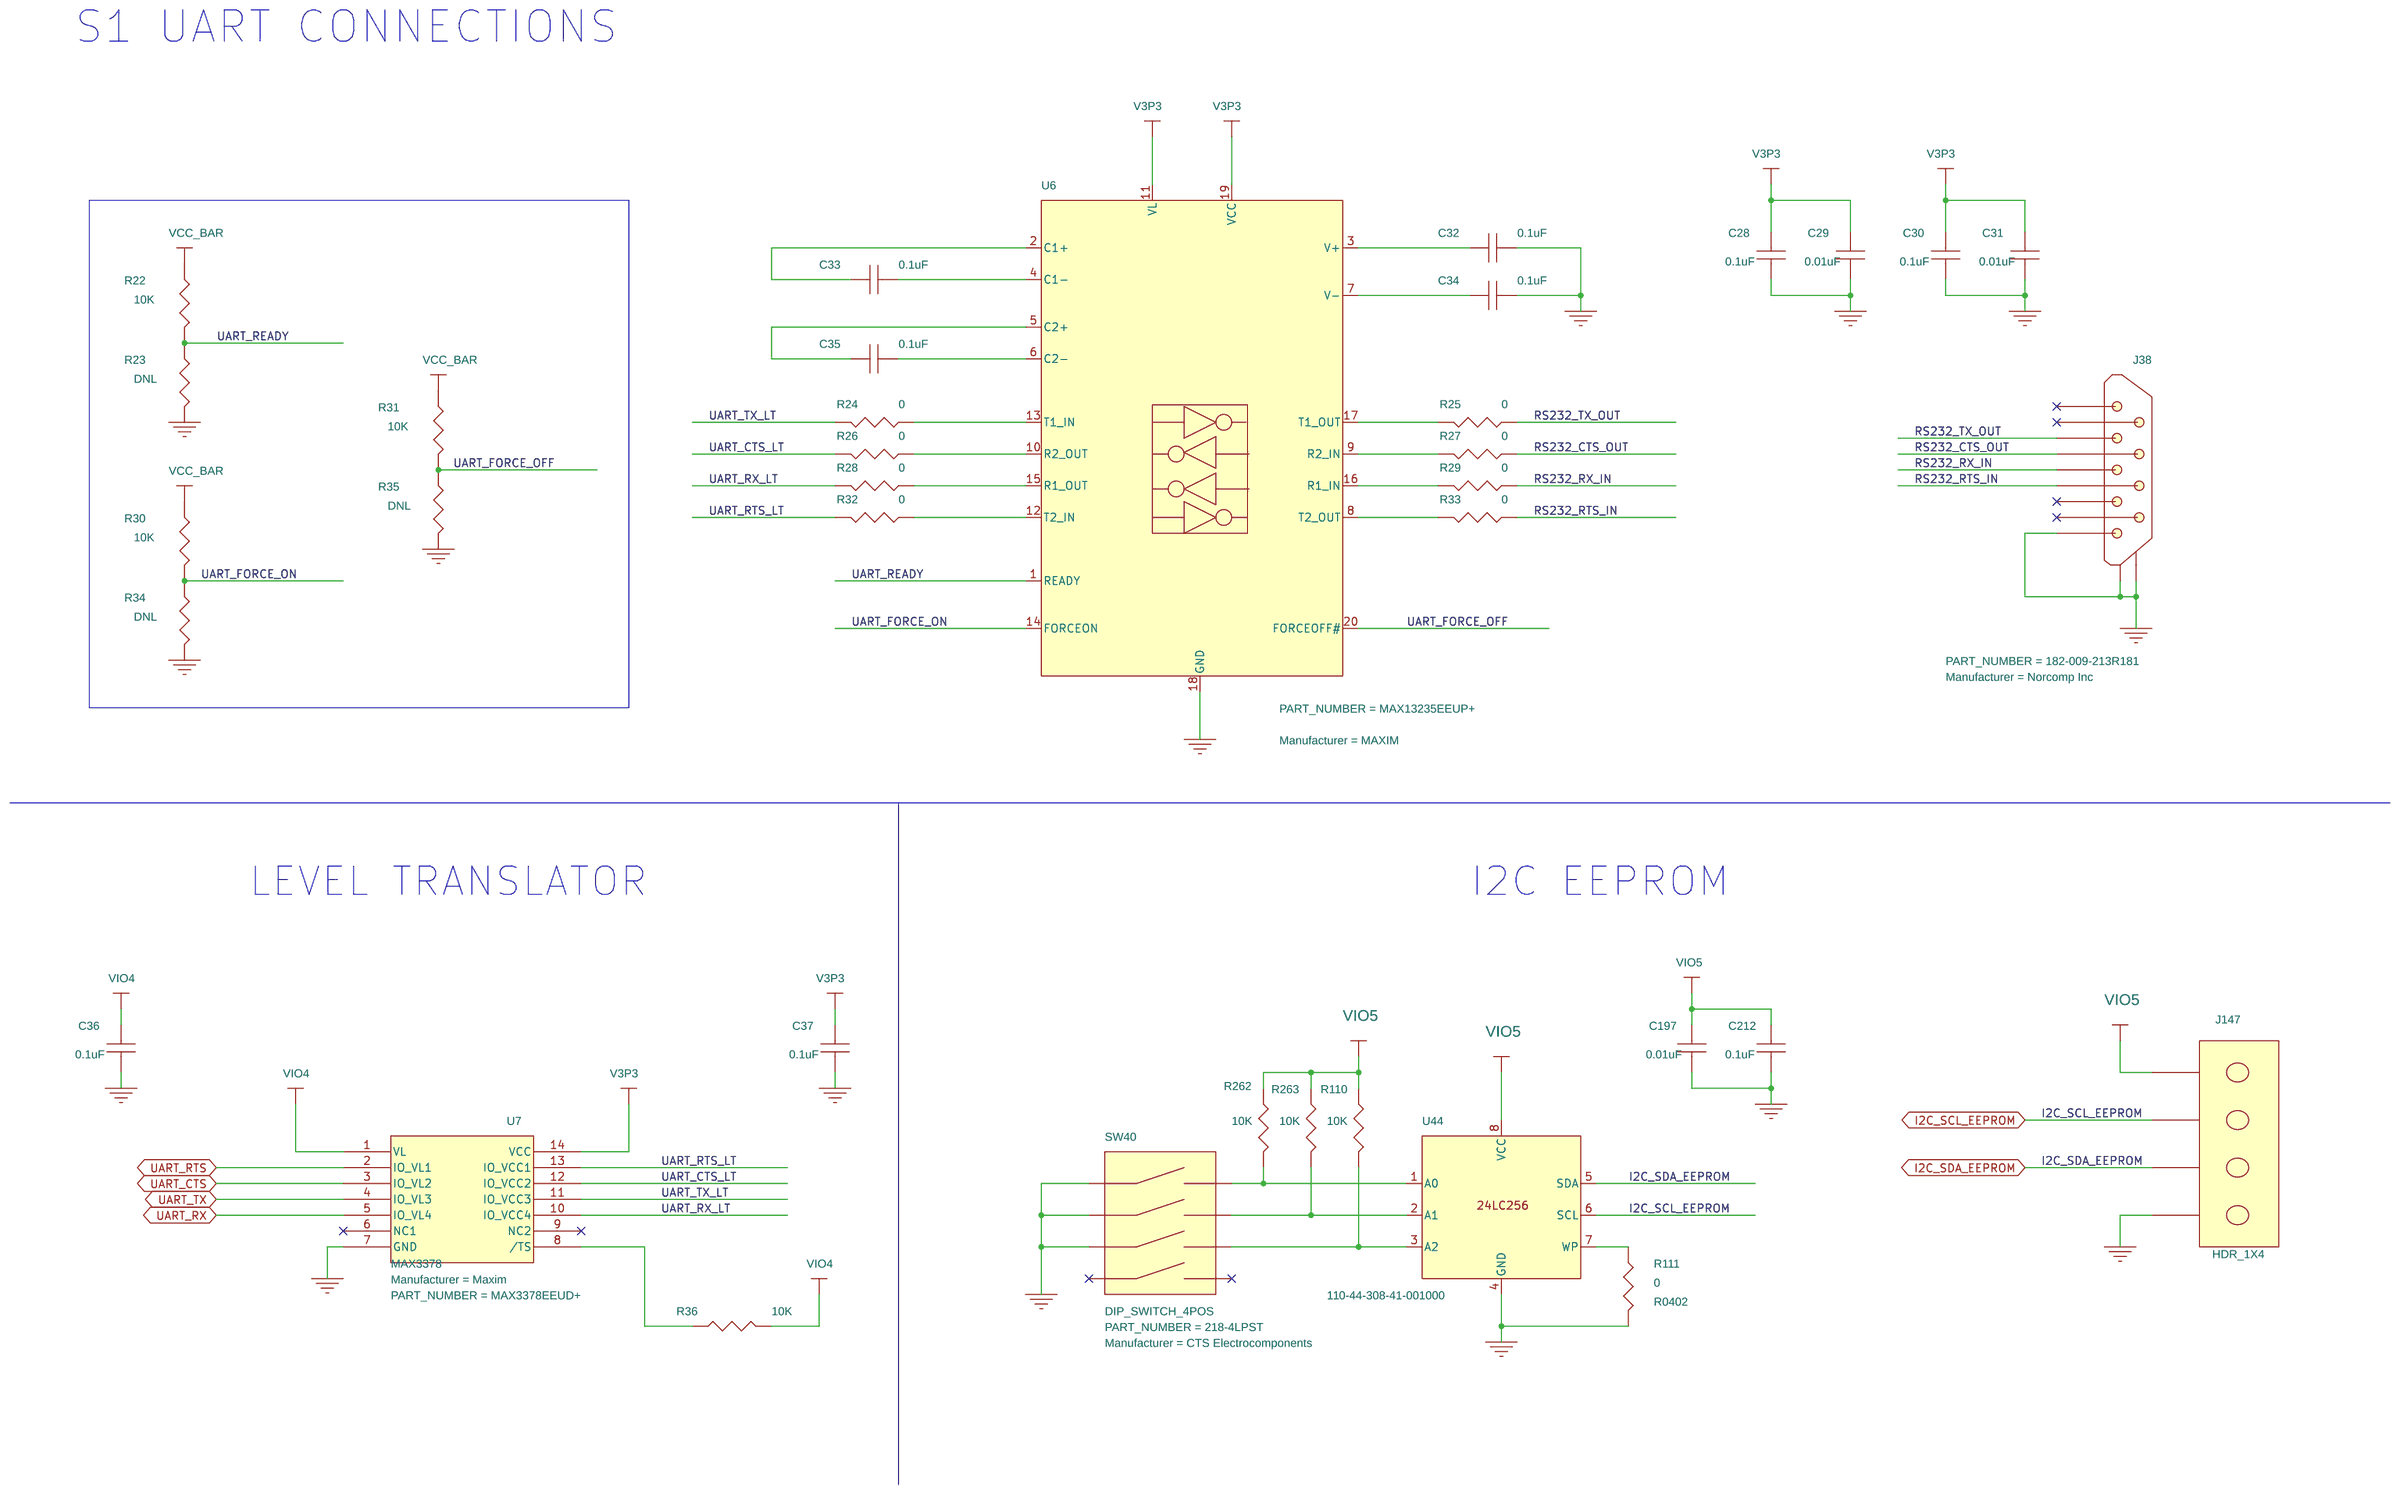
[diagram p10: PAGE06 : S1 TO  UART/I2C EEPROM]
12 PAGE05 : S0/S1 PORT CONNECTIONS: size B; rev: 2.0; note: 630-60013-01 REV02
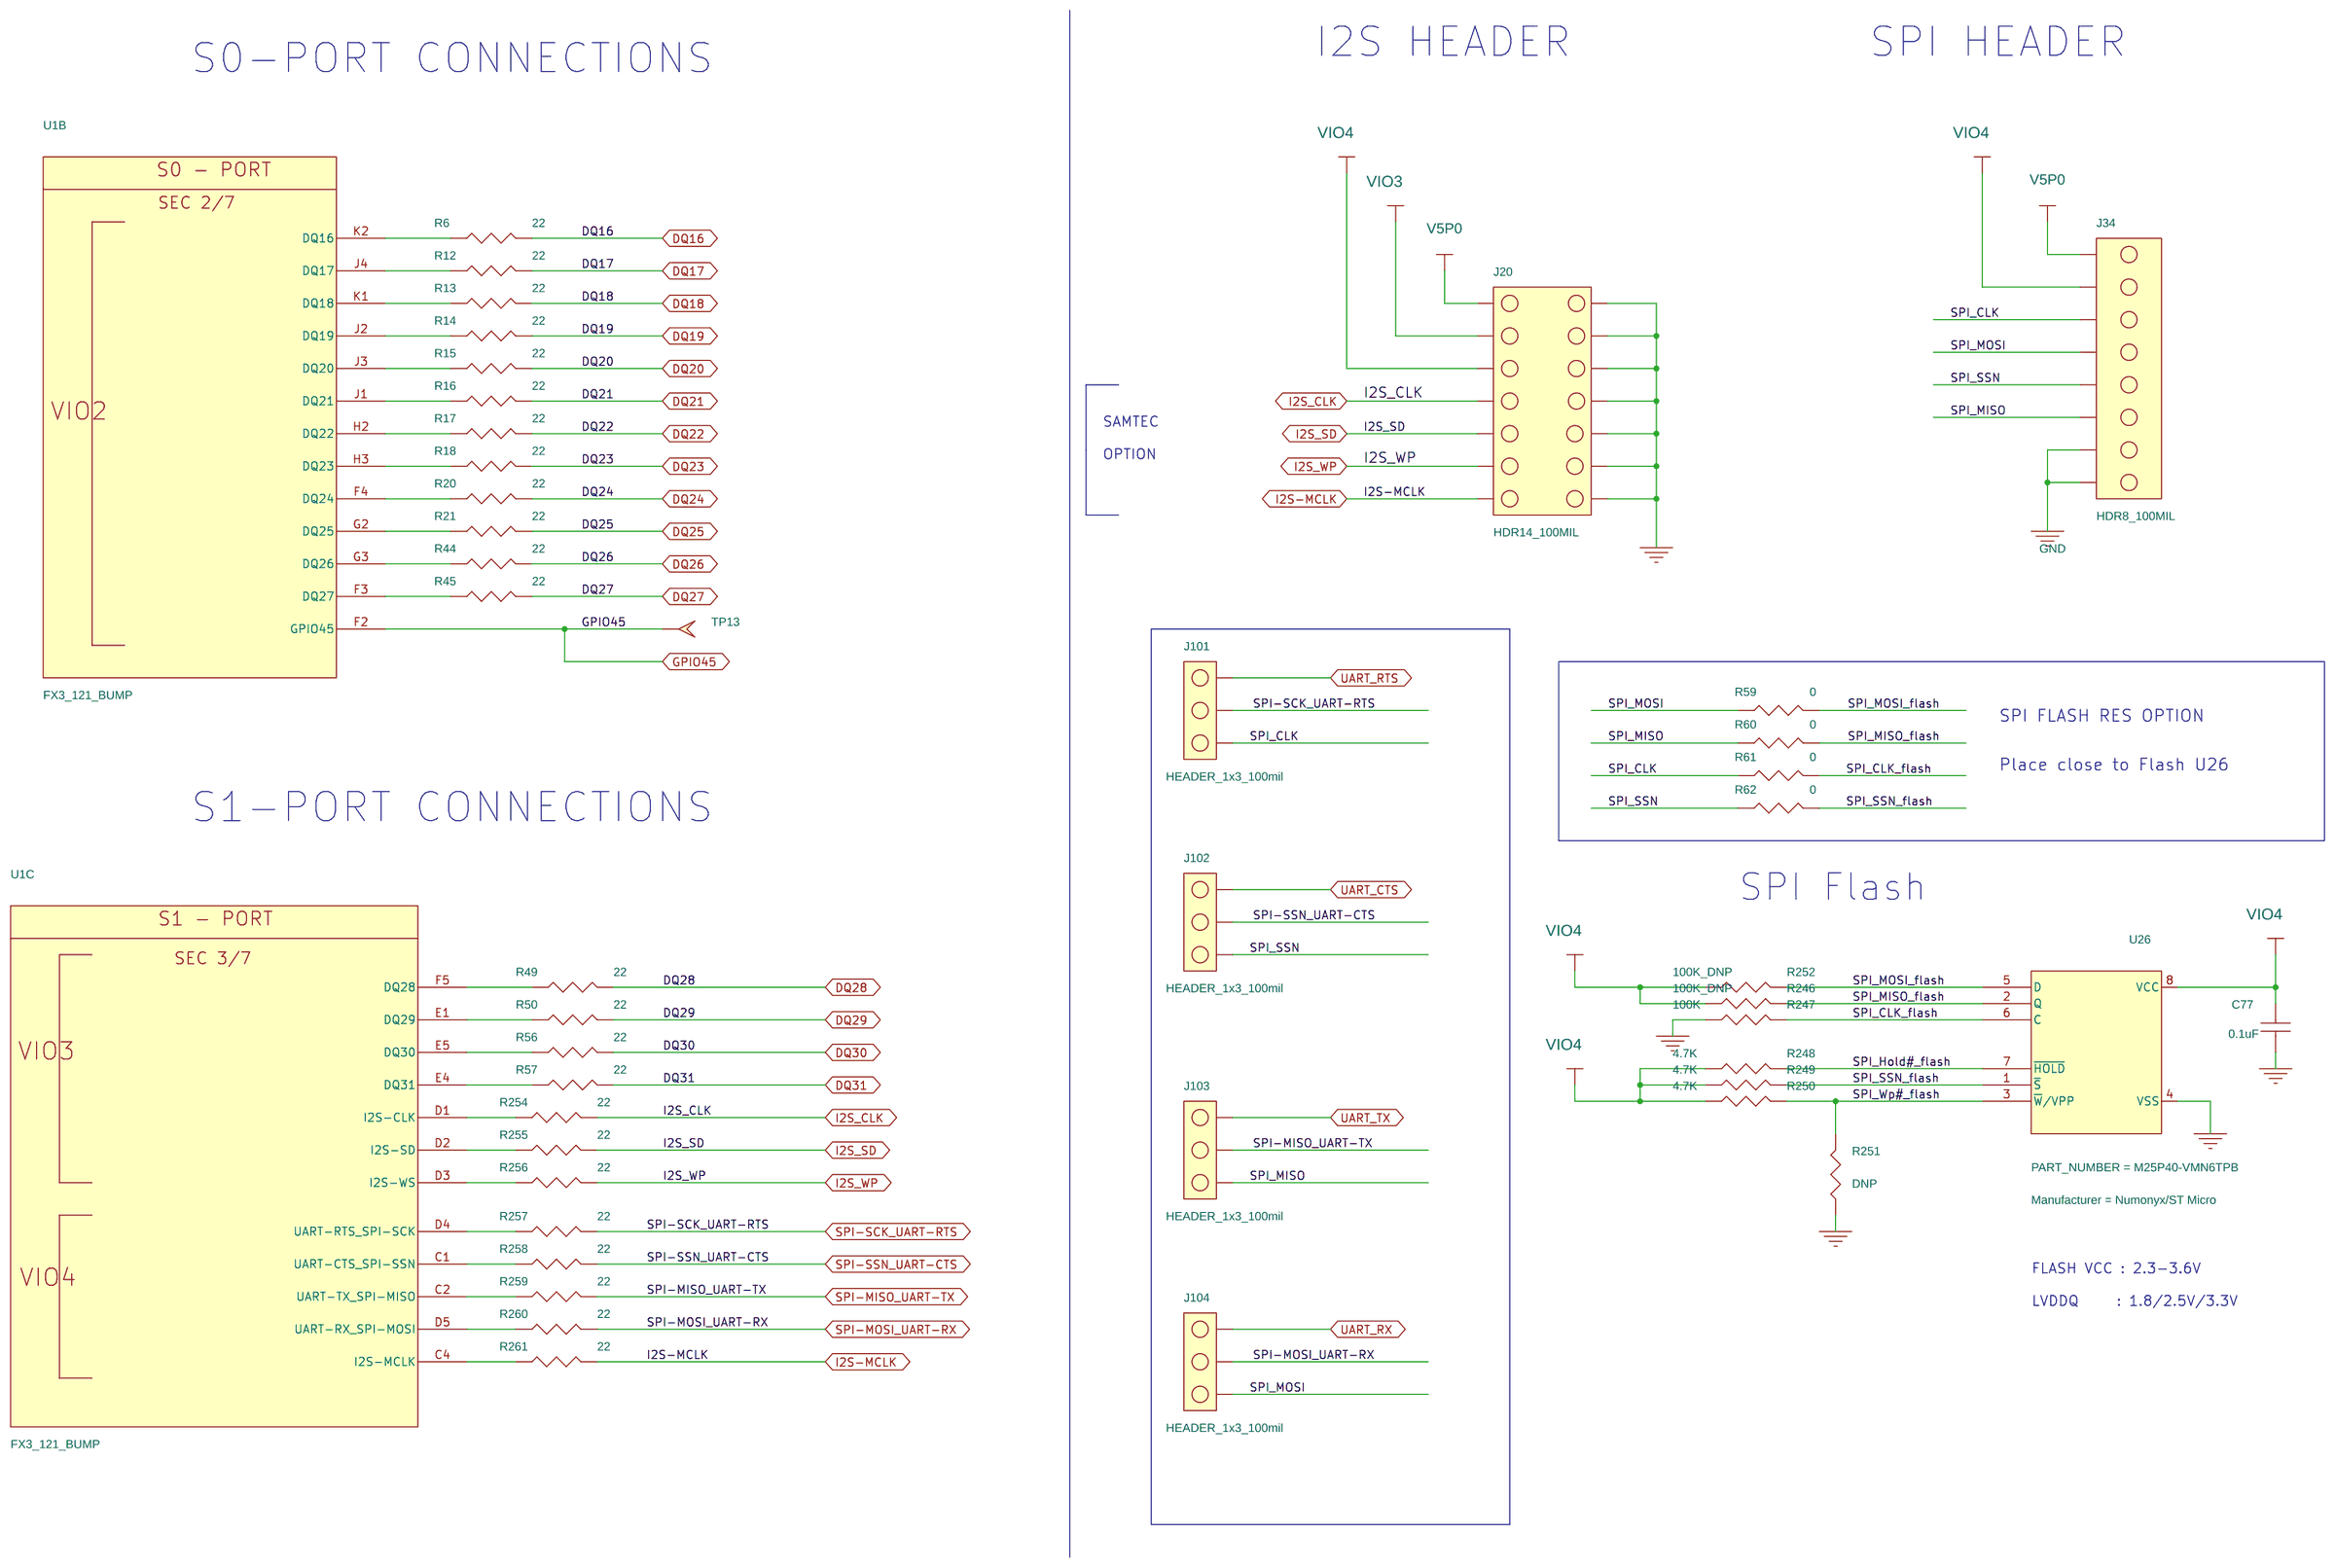
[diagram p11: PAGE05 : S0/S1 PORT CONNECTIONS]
13 PAGE11 : 5V IN / 3.3V &2.5V REG: size B
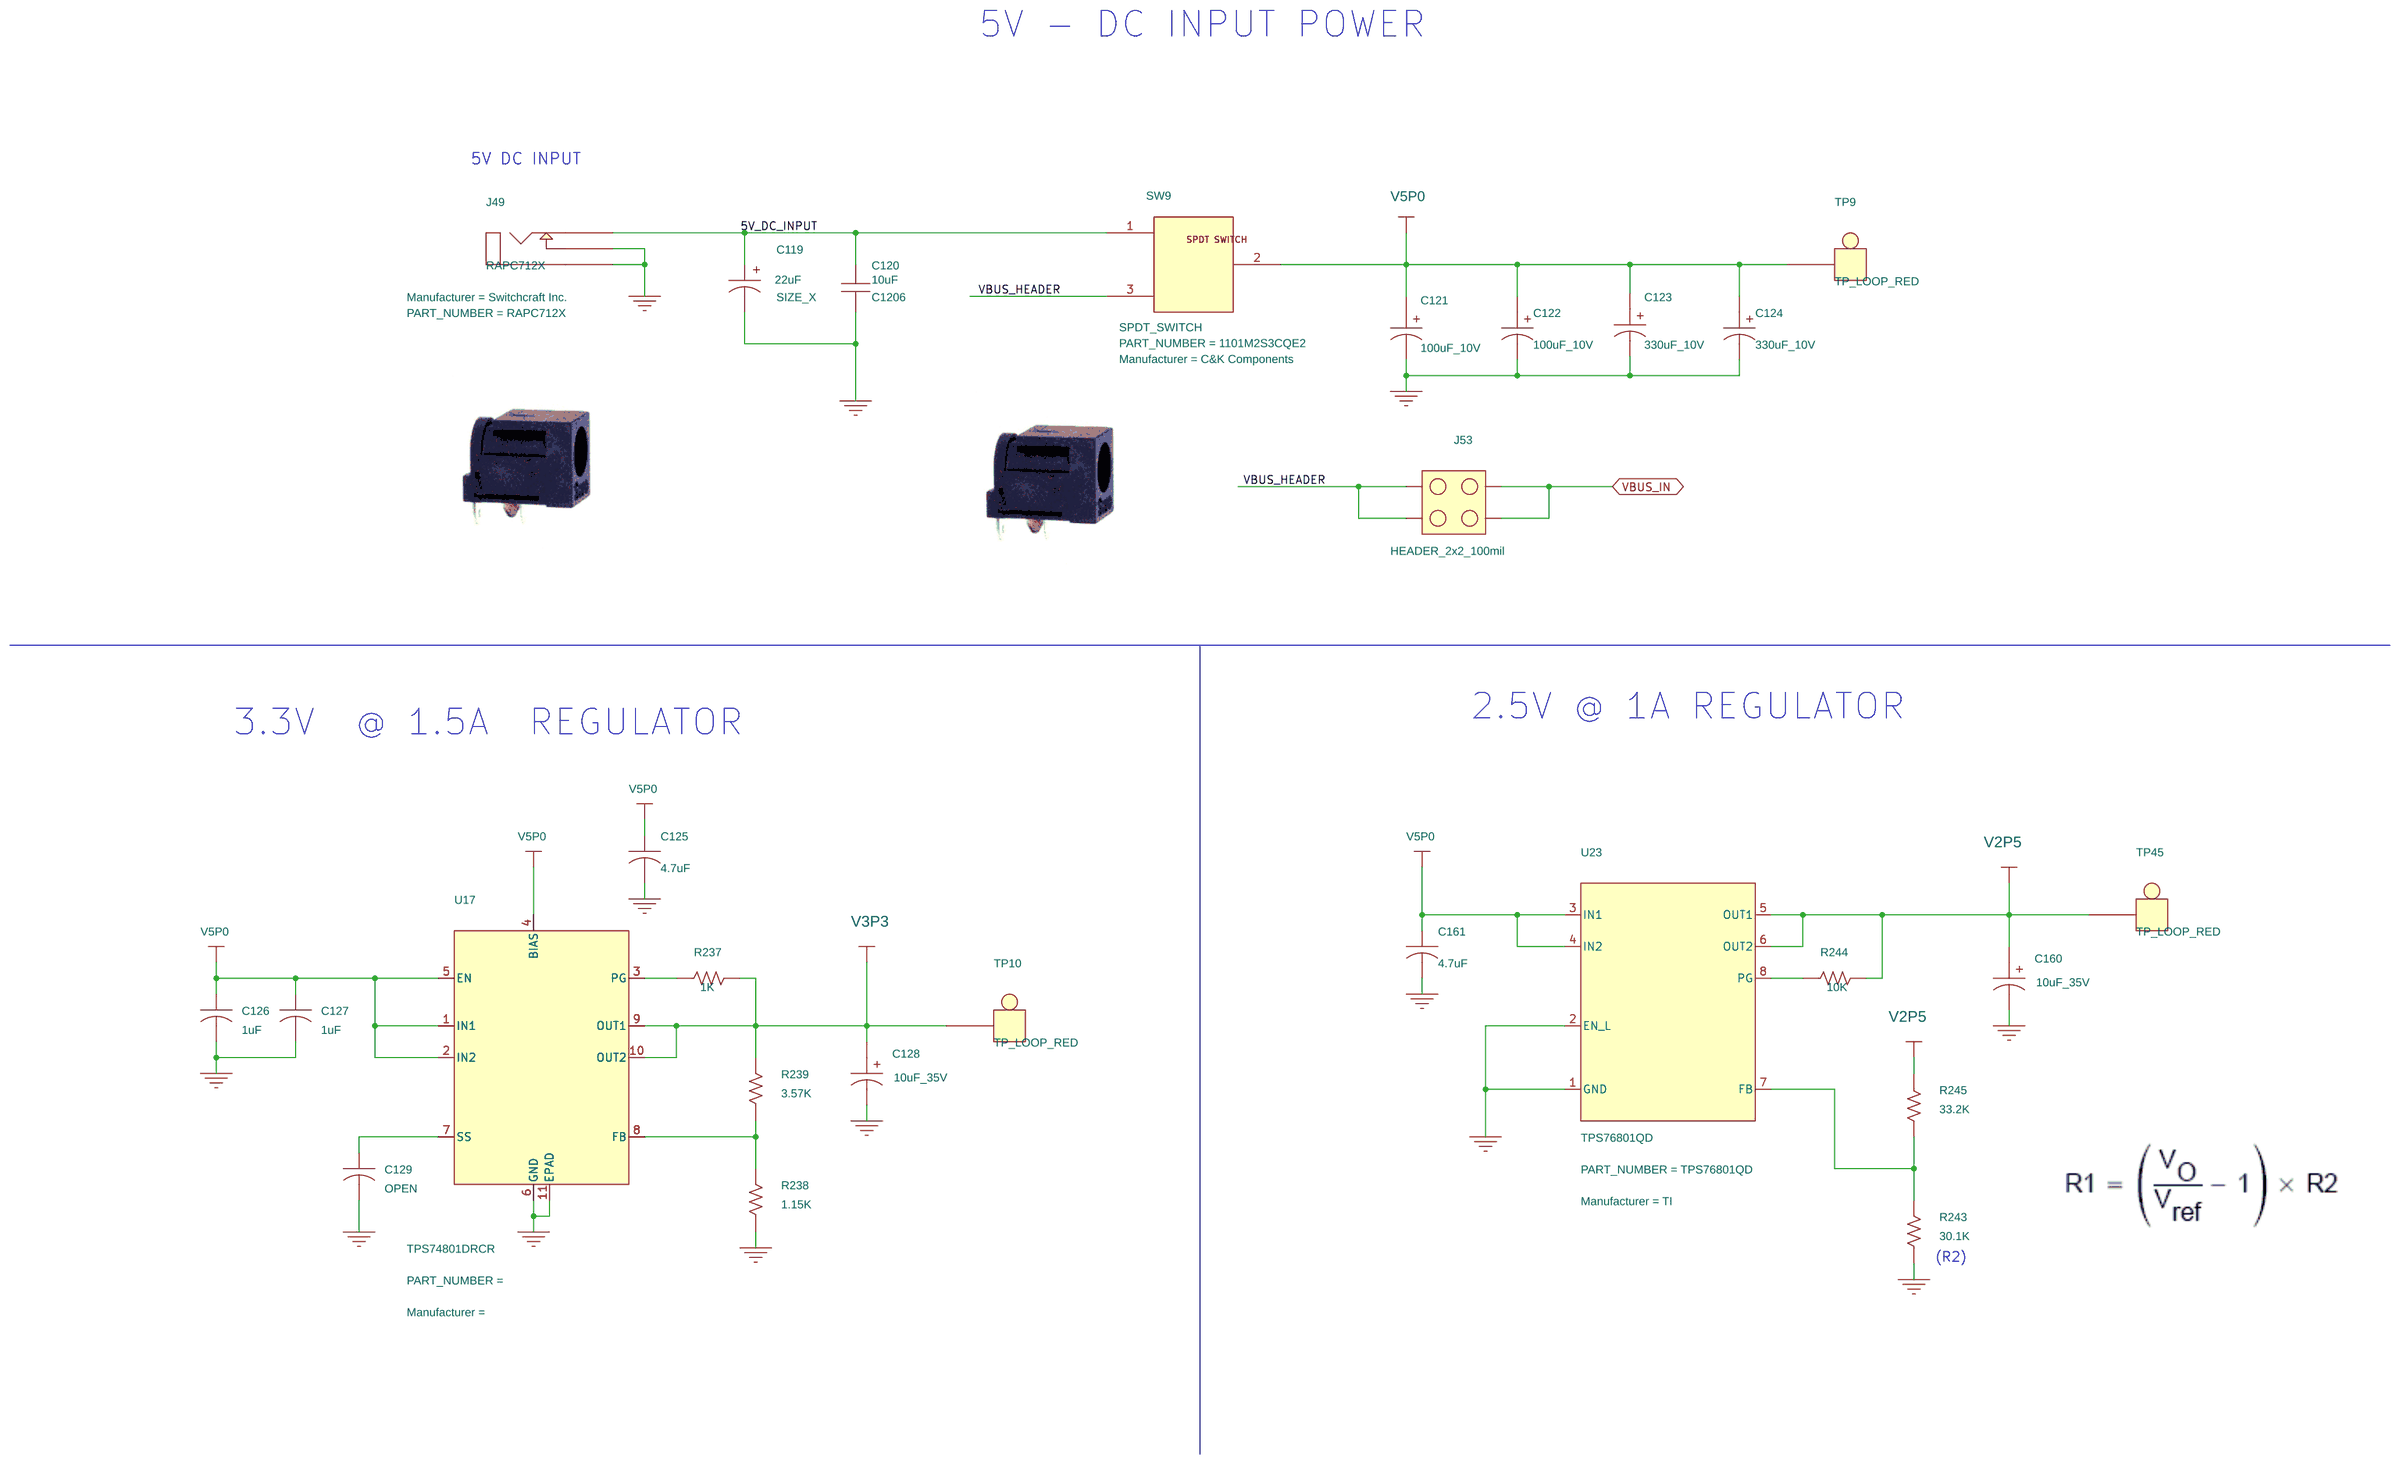
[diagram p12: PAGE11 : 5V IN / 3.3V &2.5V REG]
14 PAGE12 : 1.2V / 1.8V REGULATORS: size B
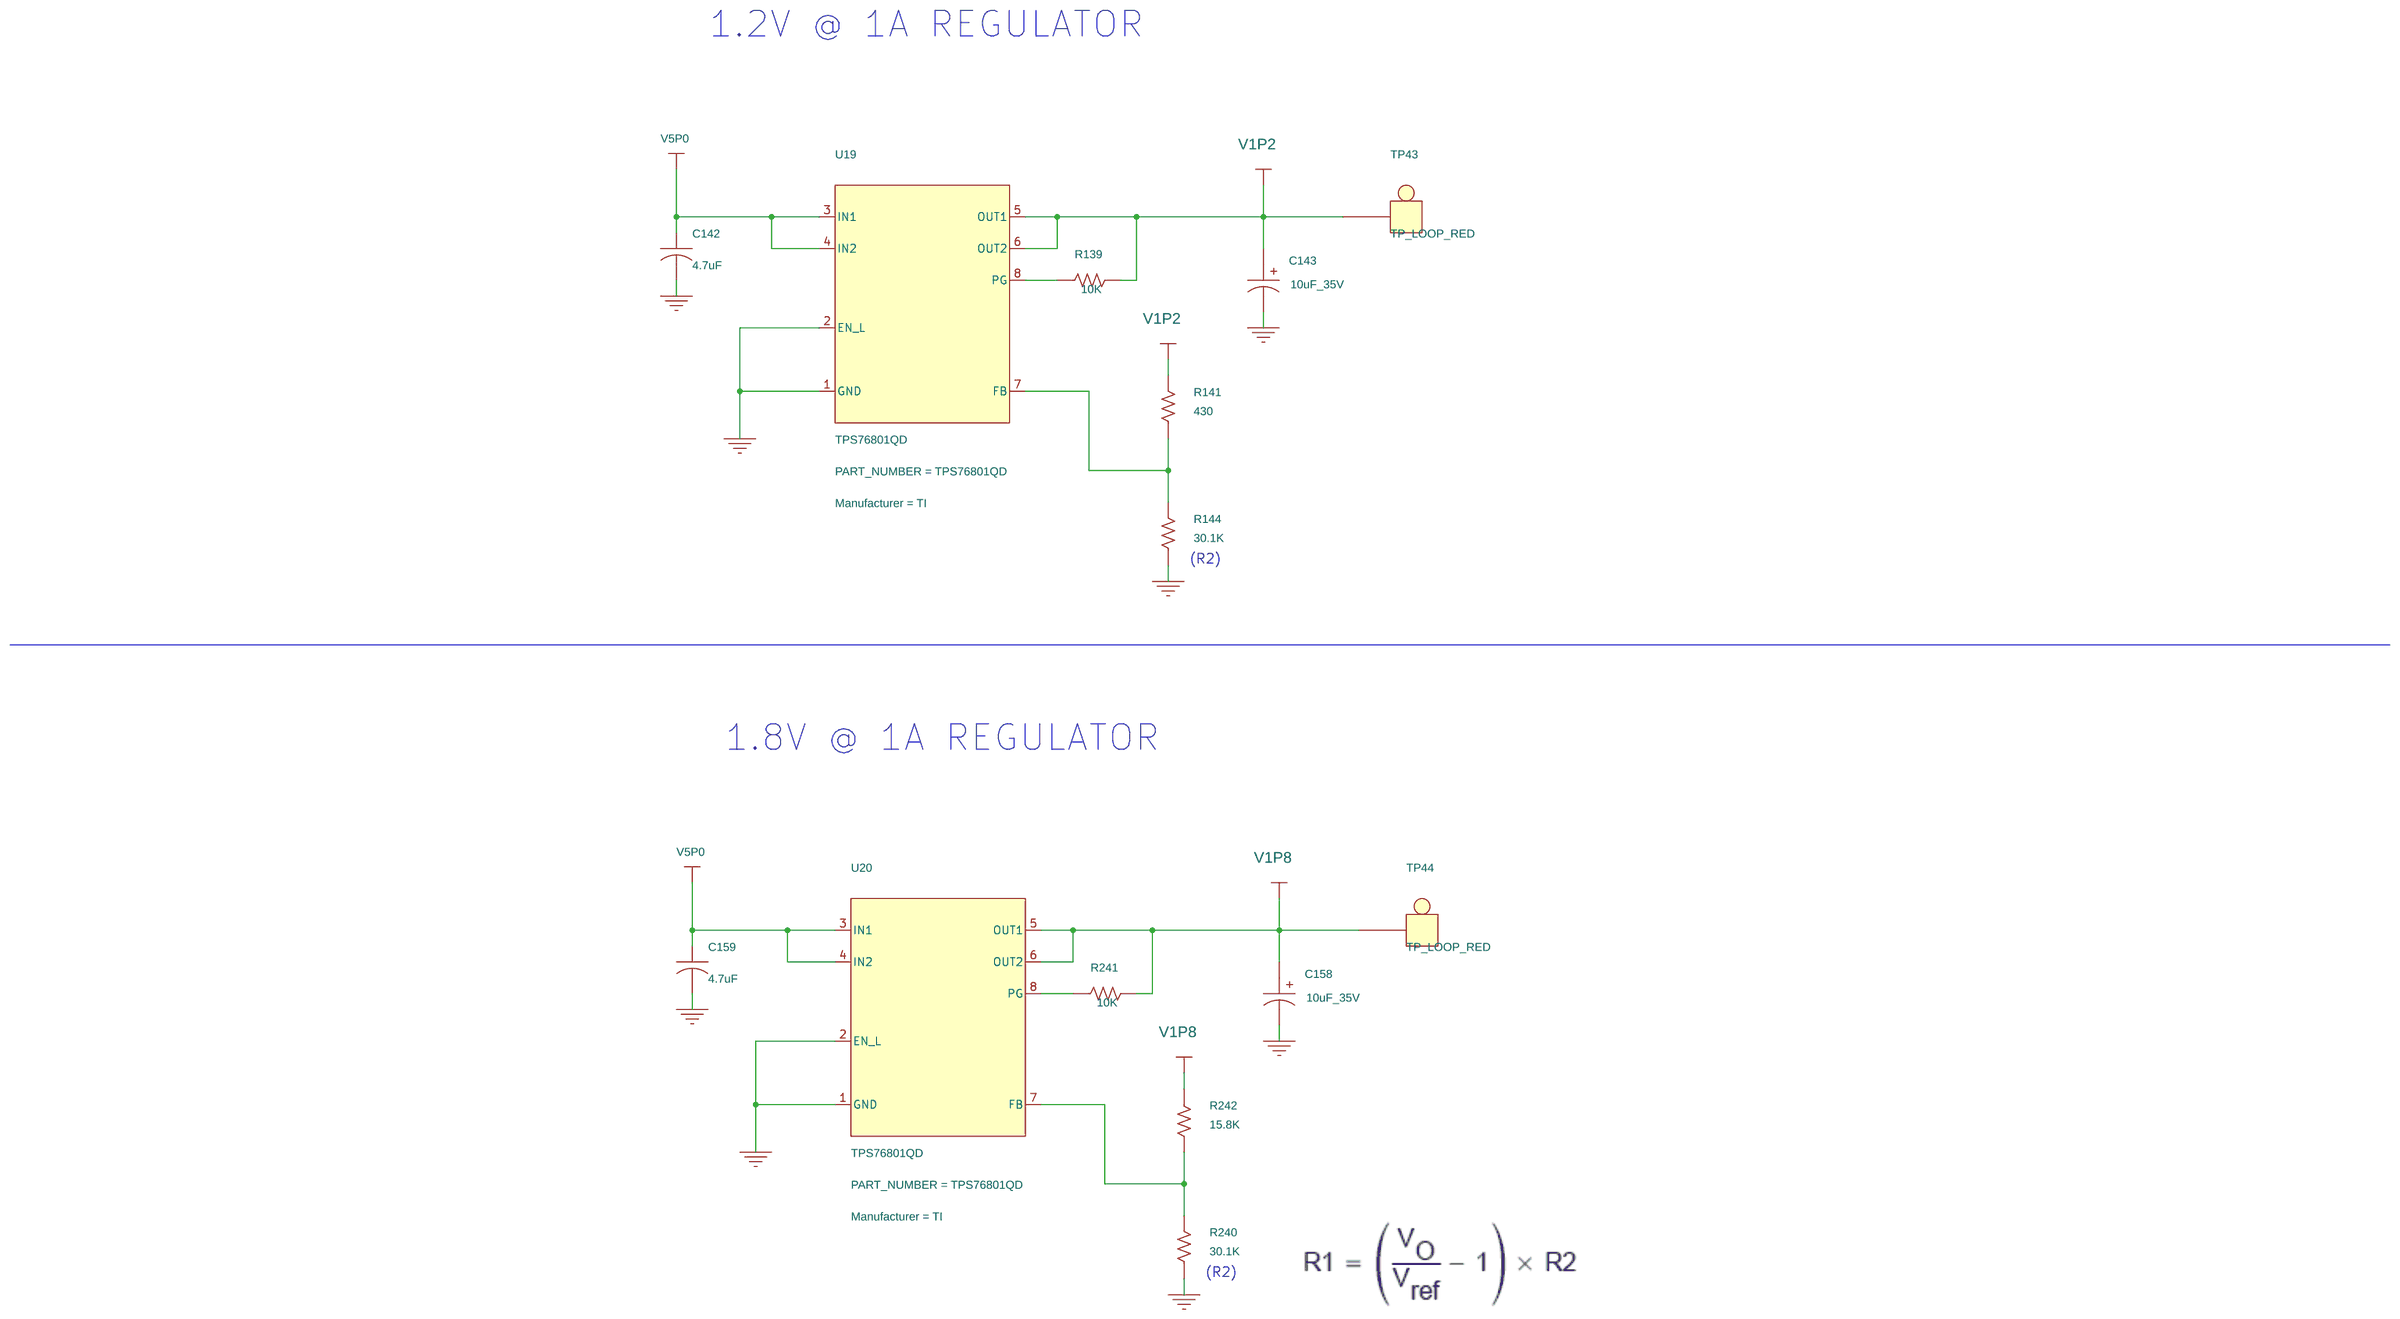
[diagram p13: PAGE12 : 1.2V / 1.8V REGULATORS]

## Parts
sheet PAGE02 : P-PORT CONNECTIONS 1
C1  0.1uF  [C0402]
C2  0.1uF  [C0402]
C3  0.1uF  [C0402]
J72  HEADER_1x3_100mil  [HEADER_1x3_100mil]
J96  HEADER_1x3_100mil  [HEADER_1x3_100mil]
J97  HEADER_1x3_100mil  [HEADER_1x3_100mil]
J98  HEADER_1x3_100mil  [HEADER_1x3_100mil]
J100  HEADER_1x3_100mil  [HEADER_1x3_100mil]
R5  22  [R0402]
R7  10K  [R0402]
R8  10K  [R0402]
R10  10K  [R0402]
R11  10K  [R0402]
R19  10K  [R0402]
R63  100K  [R0402]
R170  DNL  [R0402]
R205  22  [R0402]
R206  22  [R0402]
R207  22  [R0402]
R208  22  [R0402]
R209  22  [R0402]
R210  22  [R0402]
R211  22  [R0402]
R212  22  [R0402]
R213  22  [R0402]
R214  22  [R0402]
R215  22  [R0402]
R216  22  [R0402]
R217  22  [R0402]
R218  22  [R0402]
R219  22  [R0402]
R220  22  [R0402]
R221  22  [R0402]
R222  22  [R0402]
R223  22  [R0402]
R224  22  [R0402]
R225  22  [R0402]
R226  22  [R0402]
R227  22  [R0402]
R228  22  [R0402]
R229  22  [R0402]
R230  22  [R0402]
R231  22  [R0402]
R232  22  [R0402]
R233  22  [R0402]
R234  22  [R0402]
R235  22  [R0402]
R236  22  [R0402]
SW8  PBSwitch  [PUSHBUTTON_EVQ]
SW25  DIP_SWITCH_4POS  [SPST4_DIP_218-4LPST]
U45  BI_LVL_TRANS_1BIT  [SOT23_6_TXS0101]
sheet PAGE03 : P/S0/S1 PORT TO SAMTEC
J77  QSH_120pin_CONN  [QSH-060-01-L-D-A]  (sections A,B)
J125  HEADER_1x2_100mil  [HEADER_1x2_100mil]
J156  HEADER_1x2_100mil  [HEADER_1x2_100mil]
sheet PAGE04 : MICTOR CONNECTIONS
J1  2-5767004-2  [2-5767004-2]
J2  2-5767004-2  [2-5767004-2]
sheet PAGE05 : S0/S1 PORT CONNECTIONS
C77  0.1uF  [C0402]
J20  HDR14_100MIL  [HDR2x7_100MIL]
J34  HDR8_100MIL  [HDR1x8_100MIL]
J101  HEADER_1x3_100mil  [HEADER_1x3_100mil]
J102  HEADER_1x3_100mil  [HEADER_1x3_100mil]
J103  HEADER_1x3_100mil  [HEADER_1x3_100mil]
J104  HEADER_1x3_100mil  [HEADER_1x3_100mil]
R6  22  [R0402]
R12  22  [R0402]
R13  22  [R0402]
R14  22  [R0402]
R15  22  [R0402]
R16  22  [R0402]
R17  22  [R0402]
R18  22  [R0402]
R20  22  [R0402]
R21  22  [R0402]
R44  22  [R0402]
R45  22  [R0402]
R49  22  [R0402]
R50  22  [R0402]
R56  22  [R0402]
R57  22  [R0402]
R59  0  [R0402]
R60  0  [R0402]
R61  0  [R0402]
R62  0  [R0402]
R246  100K_DNP  [R0402]
R247  100K  [R0402]
R248  4.7K  [R0402]
R249  4.7K  [R0402]
R250  4.7K  [R0402]
R251  DNP  [R0402]
R252  100K_DNP  [R0402]
R254  22  [R0402]
R255  22  [R0402]
R256  22  [R0402]
R257  22  [R0402]
R258  22  [R0402]
R259  22  [R0402]
R260  22  [R0402]
R261  22  [R0402]
TP13  TP_4060  [TEST_POINT_40-60]
U1  FX3_121_BUMP  [FX3_121_BUMP]  (sections A,B,C,D,E,F,G)
U26  M25P40-VMN6TPB  [M25P40-VMN6TPB_SO8]
sheet PAGE06 : S1 TO  UART/I2C EEPROM
C28  0.1uF  [C0402]
C29  0.01uF  [C0402]
C30  0.1uF  [C0402]
C31  0.01uF  [C0402]
C32  0.1uF  [C0402]
C33  0.1uF  [C0402]
C34  0.1uF  [C0402]
C35  0.1uF  [C0402]
C36  0.1uF  [C0402]
C37  0.1uF  [C0402]
C197  0.01uF  [C0402]
C212  0.1uF  [C0402]
J38  182-009-213R181  [182-009-213R181]
J147  HDR_1X4  [HDR_1X4_100MIL]
R22  10K  [R0402]
R23  DNL  [R0402]
R24  0  [R0402]
R25  0  [R0402]
R26  0  [R0402]
R27  0  [R0402]
R28  0  [R0402]
R29  0  [R0402]
R30  10K  [R0402]
R31  10K  [R0402]
R32  0  [R0402]
R33  0  [R0402]
R34  DNL  [R0402]
R35  DNL  [R0402]
R36  10K  [R0402]
R110  10K  [R0402]
R111  0  [R0402]
R262  10K  [R0402]
R263  10K  [R0402]
SW40  DIP_SWITCH_4POS  [SPST4_DIP_218-4LPST]
U6  MAX13235EEUP+  [MAX13235_TSSOP20]
U7  MAX3378  [TSSOP14]
U44  110-44-308-41-001000  [110-44-308-41-001000]
sheet PAGE07 : CLOCK SIGNALS
C39  0.1uF  [C0402]
C216  12pF  [C0805]
C217  12pF  [C0805]
R37  10K  [R0402]
R38  10K  [R0402]
R39  10K  [R0402]
R40  0  [R0402]
R41  10K  [R0402]
R42  10K  [R0402]
R43  33  [R0402]
R58  10K  [R0402]
TP15  TP40_SMD  [TP_SMD]
X2  OSCILLATOR - 32.768KHz  [SG_3040LC]
Y3  CRYSTAL  [xtal_ITTI]
sheet PAGE08 : JTAG CONNECTIONS
J42  HEADER_1x3_100mil  [HEADER_1x3_100mil]
J45  HEADER_1x3_100mil  [HEADER_1x3_100mil]
J51  N2520-6002-RB  [N2520-6002-RB]
J52  HEADER_1x3_100mil  [HEADER_1x3_100mil]
R51  10K  [R0402]
R52  10K  [R0402]
R53  10K  [R0402]
R54  10K  [R0402]
R55  10K  [R0402]
R176  2K  [R0402]
R186  2K  [R0402]
TP31  TP_4060  [TEST_POINT_40-60]
sheet PAGE09 : USB CONNECTIONS
C42  1uF / 50v  [EEE-1HA010NR]
C43  0.1uF  [C0402]
C44  1uF / 50v  [EEE-1HA010NR]
C45  150uF / 20V  [SIZE_X]
C46  0.1uF  [C0402]
C47  4.7uF  [TANT_0603]
C49  0.1uF  [C0402]
C185  1uF  [C0402]
C186  1uF  [C0402]
F1  FUSE 0.63A  [MFU0603FF00630P100]
J40  HEADER2_100mil  [HDR_1X2_100MIL]
J47  HEADER2_100mil  [HDR_1X2_100MIL]
J48  USB_3  [USB3_CMS1811-010010]
J50  HEADER2_100mil  [HDR_1X2_100MIL]
L1  FERRITE BEAD  [BLM21PG221SN1D]
L2  FERRITE BEAD  [BLM21PG221SN1D]
L5  FERRITE BEAD  [BLM21PG221SN1D]
R46  100K  [R0402]
R47  200 / 1%  [R0402]
R48  6.04K / 1%  [R0402]
R190  1M  [R0402]
R264  10K  [R0402]
TP28  TP_4060  [TEST_POINT_40-60]
TP46  TP_4060  [TEST_POINT_40-60]
U8  MAX1823BEUB  [MAX1823BEUB]
U9  ESD Protector  [UDFN10_SP3010]
U37  NCP361SNT1G  [NCP361SNT1G_TSOP5]
sheet PAGE10 : FX3 POWER
BT1  SR1130 (3000TR)  [SR1130_3000TR]
C53  100nF  [C0402]
C78  0.1uF  [C0201]
C79  0.1uF  [C0201]
C80  0.1uF  [C0201]
C81  0.01uF  [C0201]
C82  0.01uF  [C0201]
C83  0.1uF  [C0201]
C84  0.1uF  [C0201]
C85  0.01uF  [C0201]
C86  0.1uF  [C0201]
C87  0.1uF  [C0201]
C88  0.01uF  [C0201]
C89  0.1uF  [C0201]
C90  0.01uF  [C0201]
C91  0.1uF  [C0201]
C92  2.2 uF  [C0603]
C102  0.1uF  [C0201]
C103  2.2 uF  [C0603]
C104  0.1uF  [C0201]
C105  2.2 uF  [C0603]
C106  0.1uF  [C0201]
C107  0.01uF  [C0201]
C108  0.1uF  [C0201]
C109  0.01uF  [C0201]
C110  0.1uF  [C0201]
C111  0.01uF  [C0201]
C112  0.1uF  [C0201]
C113  0.01uF  [C0201]
C114  0.1uF  [C0201]
C115  0.01uF  [C0201]
D1  BAT54C  [SOT23-BAT54C-7-F]
J74  HDR_1X2_100MIL  [HDR_1X2_100MIL]
TP11  TP_LOOP_BLACK  [TP_BLACK_5001]
TP12  TP_LOOP_BLACK  [TP_BLACK_5001]
TP14  TP_LOOP_BLACK  [TP_BLACK_5001]
TP16  TP_LOOP_BLACK  [TP_BLACK_5001]
TP17  TP_LOOP_BLACK  [TP_BLACK_5001]
TP18  TP_LOOP_BLACK  [TP_BLACK_5001]
TP19  TP_LOOP_BLACK  [TP_BLACK_5001]
sheet PAGE11 : 5V IN / 3.3V &2.5V REG
C119  22uF  [SIZE_X]
C120  10uF  [C1206]
C121  100uF_10V  [C3528_TAJB107M010RNJ]
C122  100uF_10V  [C3528_TAJB107M010RNJ]
C123  330uF_10V  [C7343_TAJD337K010RNJ]
C124  330uF_10V  [C7343_TAJD337K010RNJ]
C125  4.7uF  [TANT_0603]
C126  1uF  [C0402]
C127  1uF  [C0402]
C128  10uF_35V  [SIZED]
C129  OPEN  [C0402]
C160  10uF_35V  [SIZED]
C161  4.7uF  [TANT_0603]
J49  RAPC712X  [RAPC712]
J53  HEADER_2x2_100mil  [HEADER_2x2_100mil]
R237  1K  [R0402]
R238  1.15K  [R0402]
R239  3.57K  [R0402]
R243  30.1K  [R0402]
R244  10K  [R0402]
R245  33.2K  [R0402]
SW9  SPDT_SWITCH  [SPDT_POWER_SWITCH]
TP9  TP_LOOP_RED  [TP_RED_5000]
TP10  TP_LOOP_RED  [TP_RED_5000]
TP45  TP_LOOP_RED  [TP_RED_5000]
U17  TPS74801DRCR  [TPS74801DRCR]
U23  TPS76801QD  [SOIC8_TPS76801QD]
sheet PAGE12 : 1.2V / 1.8V REGULATORS
C142  4.7uF  [TANT_0603]
C143  10uF_35V  [SIZED]
C158  10uF_35V  [SIZED]
C159  4.7uF  [TANT_0603]
R139  10K  [R0402]
R141  430  [R0402]
R144  30.1K  [R0402]
R240  30.1K  [R0402]
R241  10K  [R0402]
R242  15.8K  [R0402]
TP43  TP_LOOP_RED  [TP_RED_5000]
TP44  TP_LOOP_RED  [TP_RED_5000]
U19  TPS76801QD  [SOIC8_TPS76801QD]
U20  TPS76801QD  [SOIC8_TPS76801QD]
sheet PAGE13 : POWER HEADERS
FB1  MPZ2012S601A  [FB0805]
FB2  MPZ2012S601A  [FB0805]
FB4  MPZ2012S601A  [FB0805]
FB5  MPZ2012S601A  [FB0805]
J134  HEADER_4x2_100mil  [HEADER_4x2_100mil]
J135  HEADER_2x2_100mil  [HEADER_2x2_100mil]
J136  HEADER_3x2_100mil  [HEADER_3x2_100mil]
J143  HEADER_3x2_100mil  [HEADER_3x2_100mil]
J144  HEADER_3x2_100mil  [HEADER_3x2_100mil]
J145  HEADER_3x2_100mil  [HEADER_3x2_100mil]
J146  HEADER_3x2_100mil  [HEADER_3x2_100mil]
sheet PAGE14 : Power LED
D14  LED  [LED_0603]
D15  LED  [LED_0603]
D16  LED  [LED_0603]
D17  LED  [LED_0603]
D18  LED  [LED_0603]
Q13  MMBT3904  [SOT23_MMBT]
Q14  MMBT3904  [SOT23_MMBT]
Q15  MMBT3904  [SOT23_MMBT]
Q16  MMBT3904  [SOT23_MMBT]
Q17  MMBT3904  [SOT23_MMBT]
R300  1K  [R0402]
R301  180  [R0402]
R302  180  [R0402]
R306  1K  [R0402]
R307  180  [R0402]
R308  1K  [R0402]
R309  180  [R0402]
R310  1K  [R0402]
R311  180  [R0402]
R312  1K  [R0402]

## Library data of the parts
C1-C3 = CAPACITOR_NON-POL: CAP - CER, 0.1uF, 0402, 25VDC, Y5V; Manufacturer: Murata; PART_NUMBER: GRM155F51E104ZA01D
J72 J96-J98 J100-J104 = HEADER_1x3_100mil: LOAD: DEFAULT : PIN 2-3
R5 R6 R12-R18 R20 R21 R44 R45 R49 R50 R56 R57 R205-R236 R254-R261 = R_v2: RES 22.0 OHM 1/10W 1% 0402 SMD; Manufacturer: Panasonic - ECG; Manufaturer: Panasonic - ECG; PART_NUMBER: ERJ-2RKF22R0X
R7 R8 R19 R22 R30 R31 R36 R41 R42 R51-R55 R58 R170 = R_v2: RES 10.0K OHM 1/16W 1% 0402 SMD; Manufacturer: Vishay; Manufaturer: Vishay; PART_NUMBER: CRCW040210K0FKED
R10 R11 = RESISTOR: RES 10.0K OHM 1/16W 1% 0402 SMD; Manufacturer: Vishay; Manufaturer: Vishay; PART_NUMBER: CRCW040210K0FKED
R46 R63 R246 R247 R252 = R_v2: RES 100K OHM 1/10W 1% 0402 SMD; Manufacturer: PANASONIC; PART_NUMBER: ERJ-2RKF1003X
SW8 = EVQPAC07K_0: 6MM LIGHT TOUCH SW H=7; FPLIST: PBSPST,PUSHBUTTON_EVQ; Item Num: P11-24000R; Lead Free Status: No; Manufacturer: Panasonic; Manufacturer Part Num: EVQPAC07K; Mfr Code: PAN; Num Pins: 4; PART_NUMBER: EVQPAC07K; Part Class: Switches; Price: 0.1; RoHS Compliant: Yes
SW25 SW40 = DIP_SWITCH4: SWITCH DIP HALF PITCH 4POS; Manufacturer: CTS Electrocomponents; Manufavturer: CTS Electrocomponents; PART_NUMBER: 218-4LPST
U45 = BI_LVL_TRANS_1BIT
J77 = QTH120_CONN: CONN RCPT HI-SPD .5MM 120POS DL
J125 J156 = HEADER2
J1 J2 = MICTOR_HEADER_1: CONN RECEPT 38POS .025 VERT SMD; CLASS: IO; GDA Part No: GJ00-00000001-0038; Manufacturer: TEConnectivity; Mfg: TEConnectivity; Mfg Part No: 2-767004-2
C28 C30 C32-C37 C39 C43 C46 C49 C77 C212 = Cap: CAP CER .1UF 16V X7R 0402; FPLIST: 0201_rnd,0201; Manufacturer: Murata; PART_NUMBER: GRM155R71C104KA88D; Tolerance: 10%
J20 = HEADER_2X7
J34 = HEADER_8
R59-R62 R111 = RESISTOR: RES ZERO OHM 1/10W 5% 0402 SMD; Manufacturer: Panasonic; PART_NUMBER: ERJ-2GE0R00X
R248-R250 = R_v2: RES 4.70K OHM 1/10W 1% 0402 SMD; Manufacturer: PANASONIC; PART_NUMBER: ERJ-2RKF4701X
R251 = R_v2
TP13 TP28 TP31 TP46 = T_POINT_A
U1 = FX3_121_BUMP_5
U26 = M25P32-VMW6G: IC FLASH 4MBIT 75MHZ 8SOIC; Manufacturer: Numonyx/ST Micro
C29 C31 C197 = Cap: CAP CERM .01UF 10% 25V X7R 0402; FPLIST: 0201_rnd,0201; Manufacturer: AVX; PART_NUMBER: 04023C103KAT2A; Tolerance: 10%
J38 = DSUB_0: CONN DB9 FEMALE .318" R/A NICKEL; Manufacturer: Norcomp Inc; RoHS Compliant?: YES
J147 = HDR_1X4
R23 R34 R35 = R_v2: DO NOT LOAD
R24-R29 R32 R33 R40 = R_v2: RES ZERO OHM 1/10W 5% 0402 SMD; Manufacturer: Panasonic; PART_NUMBER: ERJ-2GE0R00X
R110 R262-R264 = RESISTOR: RES 10.0K OHM 1/16W 1% 0402 SMD; Manufacturer: Vishay; PART_NUMBER: CRCW040210K0FKED
U6 = MAX13235EEUP_0: TXRX RS-232 3MBPS 2X2 20TSSOP; Height (Mils): 79.6; Manufacturer: MAXIM; Mfg: Maxim Integrated Products; Operating Temp (Degree Celsius): -40°C to 85°C; RoHS Compliant?: YES; System Name: CS/BS; System_Name: CS/BS
U7 = MAX3378_0: IC LVL XLTR LV 8MBPS 14-TSSOP; Item Num: P01-13191R; Lead Free Status: Yes; Manufacturer: Maxim; Manufacturer Part Num: MAX3378EEUD+; Num Pins: 14; PART_NUMBER: MAX3378EEUD+; Part Class: ICs; RoHS Compliant: Yes
U44 = 24LC256: IC SOCKET 8PIN MS TIN/TIN .300; Manufacturer: Mill-Max Manufacturing Corp
C216 C217 = 12_pFd_0805_1: Manufacturer: PANASONIC; PART_NUMBER: ECJ-2VC1H120J
R37-R39 = R_v2: RES 10.0K OHM 1/16W 1% 0402 SMD; BOM_IGNORE: DNL; Manufacturer: Vishay; Manufaturer: Vishay; PART_NUMBER: CRCW040210K0FKED
R43 = RESISTOR: RES 33.0 OHM 1/10W 1% 0402 SMD; Manufacturer: Panasonic; PART_NUMBER: ERJ-2RKF33R0X
TP15 = TESTPOINT: TESTPOINT SMD; Manufacturer: LOCAL; Mfr_Name: LOCAL; Part_Type: MISC\TESTPOINT; Project: G4SLIM
X2 = OSCILLATOR_2: PART_NUMBER: SG-3040LC 32.7680KB3: PURE SN
Y3 = CRYSTAL_1: Manufacturer: NDK America; PART_NUMBER: NX3225SA-19.200M-EXS00A-CS03082
J42 J45 = HEADER_1x3_100mil
J51 = 2520-6002UB: SHROUDED HEADER 20 POS STRAIGHT GOLD; Manufacturer: 3M
J52 = HEADER_1x3_100mil: LOAD: DEFAULT : PIN 2-3; SHUNT: DEFAULT : PIN 2-3
R176 R186 = R_v2: RES 2.00K OHM 1/16W 1% 0402 SMD; Manufacturer: Vishay; Manufaturer: Vishay; PART_NUMBER: CRCW04022K00FKED
C42 C44 = CAP: CAP 1UF 50V ELECT VS BI-POLAR; Manufacturer: PANASONIC
C45 = CAP: CAP TANT 150UF 20V 10% SMD; Manufacturer: KEMET; PART_NUMBER: T491X157K020AT
C47 = CAP: CAP TANT 4.7UF 16V 20% 0603; Manufacturer: Vishay/Sprague; PART_NUMBER: TR8M475M016C4000
C126 C127 C185 C186 = CAP: CAP - CER, 1uF, 10V, +/-10%, X5R, 0402; Item Num: P03-15479R; Lead Free Status: Yes; Manufacturer: Murata; Manufacturer Part Num: GRM155R61A105KE15D; Num Pins: 2; PART_NUMBER: GRM155R61A105KE15D; Part Class: CAPACITORS; RoHS Compliant: Yes
F1 = FUSE: FUSE .63A 0603 VFAST SMD; Manufacturer: Vishay/Beyschlag
J40 J47 J50 J74 = HEADER2_100mil
J48 = GSB343133HR_2: BOM_IGNORE: CUSTOMER SUPPLIED; Manufacturer: HOSIDEN; PART_NUMBER: CMS1811-010010
L1 L2 L5 = INDUCTOR_v2: FERRITE CHIP 220 OHM 2000MA 0805; Manufacturer: Murata
R47 = R_v2: RES 200 OHM 1/10W 1% 0402 SMD; Manufacturer: PANASONIC; PART_NUMBER: ERJ-2RKF2000X
R48 = R_v2: RES 6.04K OHM 1/10W 1% 0402 SMD; Manufacturer: PANASONIC; Manufaturer: Vishay; PART_NUMBER: ERJ-2RKF6041X
R190 = R_v2: RES 1.00M OHM 1/10W 1% 0402 SMD; Manufacturer: Panasonic; Manufaturer: Panasonic; PART_NUMBER: ERJ-2RKF1004X
U8 = MAX1823BEUB
U9 = AZ1065-06Q_0: TVS ARRAY ESD 4CH .45PF 8KV UDFN; Manufacturer: Littlefuse; PART_NUMBER: SP3010-04UTG
U37 = NCP361SNT1G_0: IC USB POS OVP/OC_TSOP5; Manufacturer: ON Semiconductor
BT1 = Battery_3000: HOLDER BATTERY COIN 12MM DIA SMD; Manufacturer: Keystone; Mfg: Keystone; Mfg Part#: 3000TR; PART_NUMBER: 3000TR
C53 = Cap: CAP CER .10UF 25V X5R 0402; FPLIST: 0402_rnd,0402; Manufacturer: Taiyo Yuden; Mfg: Taiyo Yuden; Mfg Part#: TMK105BJ104KV-F; PART_NUMBER: TMK105BJ104KV-F; Part Number: C1040402-X7R-10V; Tolerance: 10%
C78-C80 C83 C84 C86 C87 C89 C91 C102 C104 C106 C108 C110 C112 C114 = Cap: CAP CER .10UF 10V X5R 0201; FPLIST: 0201_rnd,0201; Manufacturer: Taiyo Yuden; PART_NUMBER: LMK063BJ104KP-F; Tolerance: 10%
C81 C82 C85 C88 C90 C107 C109 C111 C113 C115 = Cap: CAP CER 10000PF 16V Y5V 0201; FPLIST: 0201_rnd,0201; Manufacturer: TDK; PART_NUMBER: C0603Y5V1C103Z; Tolerance: 10%
C92 C103 C105 = Cap: CAP CERM 2.2UF 10V X5R 0603; FPLIST: 0603_rnd,0603; Manufacturer: Kemet; PART_NUMBER: C0603C225K8PACTU; Tolerance: 10%
D1 = BAT54C: DIODE SCHOTTKY DUAL 30V SOT23-3; Manufacturer: Diodes Inc; Mfg: Diodes Inc; Mfg Part#: BAT54C-7-F; PART_NUMBER: BAT54C-7-F; Part Number: BAT54C-7-F; Tolerance: NA
TP11 TP12 TP14 TP16-TP19 = TP_LOOP_RED: TEST POINT PC MINI .040"D BLACK; PART_NUMBER: 5001
C119 = C_0: CAPACITOR TANT 22UF 25V 20% SMD; Manufacturer: Kemet; PART_NUMBER: T496X226M025AT
C120 = CAPACITOR_NON-POL: CAP CER 10UF 25V Y5V 1206; Manufacturer: TDK; PART_NUMBER: C3216Y5V1E106Z
C121 C122 = CAP_POL: CAPACITOR TANT 100UF 10V 20% SMD; Manufacturer: AVX CORPORATION; Mfr_Name: AVX CORPORATION; Mfr_Part_Number: TAJB107M010RNJ; PART_NUMBER: TAJB107M010RNJ; Part_Type: CAPACITORS\TANTALUM
C123 C124 = CAP_POL: CAP TANTALUM 330UF 10V 10% SMD; Manufacturer: AVX CORPORATION; Mfr_Name: AVX CORPORATION; Mfr_Part_Number: TAJD337K010RNJ; PART_NUMBER: TAJD337K010RNJ; Part_Type: CAPACITORS\TANTALUM
C125 C142 C159 C161 = PCAP: CAP TANT 4.7UF 16V 20% 0603; Item Num: P03-15632R; Lead Free Status: No; Manufacturer: Vishay/Sprague; Manufacturer Part Num: TAJC475K050RNJ; Num Pins: 2; PART_NUMBER: TR8M475M016C4000; Part Class: Capacitors; RoHS Compliant: Yes
C128 C143 C158 C160 = CAP_POL: CAP TANTALUM 10UF 35V 10% SMD; Manufacturer: AVX CORPORATION; Mfr_Name: AVX CORPORATION; Mfr_Part_Number: TAJD106K035RNJ; PART_NUMBER: TAJD106K035RNJ; Part_Type: CAPACITORS\TANTALUM
C129 = CAP: DO NOT LOAD; Item Num: P03-15479R; Lead Free Status: Yes; Num Pins: 2; Part Class: CAPACITORS; RoHS Compliant: Yes
J49 = CONN_JACK_PWR: CONN - DC POWER JACK, RAPC712X, R/A, 3 PINS; Item Num: P23-35030R; Lead Free Status: Yes; Manufacturer: Switchcraft Inc.; Num Pins: 3; Part Class: Connectors; Price: 0.68; RoHS Compliant: Yes
J53 = HEADER_2x2_100mil
R237 R300 R306 R308 R310 R312 = R: RES 1.00K OHM 1/16W 1% 0402 SMD; Manufacturer: Vishay; PART_NUMBER: CRCW04021K00FKED; TOLERANCE: 1%
R238 = R: RES 1.15K OHM 1/16W 1% 0402 SMD; Manufacturer: Vishay/Dale; PART_NUMBER: CRCW04021K15FKED; TOLERANCE: 1%
R239 = R: RES 3.57K OHM 1/10W 1% 0402 SMD; Manufacturer: PANASONIC; PART_NUMBER: ERJ-2RKF3571X; TOLERANCE: 1%
R144 R240 R243 = R: RES 30.1K OHM 1/10W 1% 0402 SMD; Manufacturer: PANASONIC; PART_NUMBER: ERJ-2RKF3012X; TOLERANCE: 1%
R139 R241 R244 = R: RES 10.0K OHM 1/16W 1% 0402 SMD; Manufacturer: Vishay; Manufaturer: Vishay; PART_NUMBER: CRCW040210K0FKED; TOLERANCE: 1%
R245 = R: RES 33.2K OHM 1/10W 1% 0402 SMD; Manufacturer: PANASONIC; PART_NUMBER: ERJ-2RKF3322X; TOLERANCE: 1%
SW9 = SPDT_SWITCH_0: 3pin, SPDT,Thru Hole,Silver,Black,6A switch; Manufacturer: C&K Components; PART_NUMBER: 1101M2S3CQE2
TP9 TP10 TP43-TP45 = TP_LOOP_RED: TEST POINT PC MINI .040"D RED
U17 = TPS74801DRCR_0
U19 U20 U23 = TPS76801QD: IC ADJ 1A LDO REG 8-SOIC; Manufacturer: TI
R141 = R: RES 430 OHM 1/10W 1% 0402 SMD; Manufacturer: PANASONIC; PART_NUMBER: ERJ-2RKF4300X; TOLERANCE: 1%
R242 = R: RES 15.8K OHM 1/10W 1% 0402 SMD; Manufacturer: PANASONIC; PART_NUMBER: ERJ-2RKF1582X; TOLERANCE: 1%
FB1 FB2 FB4 FB5 = INDUCTOR: FERRITE CHIP BEAD 600 OHM SMD 2.0A; Manufacturer: TDK
J134 = PWR_HDR8
J135 = PWR_HDR4
J136 J143-J146 = PWR_HDR6
D14-D18 = LED: LED GREEN CLEAR 0603 SMD; CURRENT: 20mA; Manufacturer: Lite-On; PART_NUMBER: LTST-C190KGKT; Part Number: LTST-C190KGKT; Voltage Rating: 2V
Q13-Q17 = NPN_ECB_0: TRANSISTOR GP NPN AMP SOT-23; Manufacturer: Fairchild; PART NUMBER: FMMT3904TA
R301 R302 R307 R309 R311 = RESISTOR: RES 180 OHM 1/16W 1% 0402 SMD; Manufacturer: Vishay; PART_NUMBER: CRCW0402180RFKED

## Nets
5V_DC_INPUT: C119.1 C120.1 J49.2 SW9.1
AVDD: C102.1 C103.1 FB2.1 U1.A7(AVDD)
GND: BT1.MINUS(NEG) C1.2 C2.2 C3.2 C28.2 C29.2 C30.2 C31.2 C32.2 C34.2 C36.2 C37.2 C39.2 C42.2 C44.2 C45.2 C47.2 C49.2 C53.2 C77.2 C78.2 C79.2 C80.2 C81.2 C82.2 C83.2 C84.2 C85.2 C86.2 C87.2 C88.2 C89.2 C90.2 C91.2 C92.2 C102.2 C103.2 C104.2 C105.2 C106.2 C107.2 C108.2 C109.2 C110.2 C111.2 C112.2 C113.2 C114.2 C115.2 C119.2 C120.2 C121.2 C122.2 C123.2 C124.2 C125.2 C126.2 C127.2 C128.2 C129.2 C142.2 C143.2 C158.2 C159.2 C160.2 C161.2 C185.2 C186.2 C197.2 C212.2 C216.1 C217.2 J1.3 J1.39 J1.40 J1.41 J1.42 J1.43 J2.3 J2.39 J2.40 J2.41 J2.42 J2.43 J20.8 J20.9 J20.10 J20.11 J20.12 J20.13 J20.14 J34.7 J34.8 J38.5 J38.10 J38.11 J48.5(GND1) J48.8(GND2) J49.1 J49.3 J50.2 J51.4(GND1) J51.6(GND2) J51.8(GND3) J51.10(GND4) J51.12(GND5) J51.14(GND6) J51.16(GND7) J51.18(GND8) J51.20(GND9) J52.3 J77.121 J77.122 J77.123 J77.124 J77.125 J77.126 J77.127 J77.128 J147.4 L5.2 Q13.2(E) Q14.2(E) Q15.2(E) Q16.2(E) Q17.2(E) R23.1 R34.1 R35.1 R41.1 R42.1 R47.2 R48.2 R58.1 R111.2 R144.1 R238.1 R240.1 R243.1 R247.1 R251.1 R264.2 SW8.A1 SW8.A2 SW25.6 SW25.7 SW25.8 SW40.1 SW40.2 SW40.3 TP11.1 TP12.1 TP14.1 TP16.1 TP17.1 TP18.1 TP19.1 U1.A1(U3VSSQ) U1.A8(VSS12) U1.B7(AVSS) U1.B8(U2PLLVSSQ) U1.B9(U2AFEVSSQ) U1.D8(VSS5) U1.E2(VSS3) U1.G1(VSS1) U1.G11(VSS6) U1.K3(VSS10) U1.K4(VSS8) U1.L1(VSS2) U1.L2(VSS11) U1.L3(VSS9) U1.L6(VSS4) U1.L11(VSS7) U6.18(GND) U7.7(GND) U8.8(GND) U9.3 U9.8 U17.6(GND) U17.11(EPAD) U19.1(GND) U19.2(EN_L) U20.1(GND) U20.2(EN_L) U23.1(GND) U23.2(EN_L) U26.4(VSS) U37.2(GND) U37.3(EN_L) U44.4(GND) U45.2(GND) X2.6(GND) Y3.2 Y3.4
V1P2: C143.1 FB1.2 FB2.2 FB4.2 FB5.2 J134.1 R139.2 R141.2 R300.1 TP43.1 U19.5(OUT1) U19.6(OUT2)
V1P8: C158.1 J134.2 J135.1 J136.1 J144.1 J145.1 J146.1 R241.2 R242.1 R306.1 TP44.1 U20.5(OUT1) U20.6(OUT2)
V2P5: C160.1 J134.3 J136.2 J143.2 J144.2 J145.2 J146.2 R244.2 R245.1 R312.1 TP45.1 U23.5(OUT1) U23.6(OUT2)
V3P3: C28.1 C29.1 C30.1 C31.1 C37.1 C128.1 J134.4 J135.2 J136.3 J143.3 J144.3 J145.3 J146.3 R22.2 R30.2 R31.2 R237.2 R239.2 R308.1 TP10.1 U6.11(VL) U6.19(VCC) U7.14(VCC) U17.9(OUT1) U17.10(OUT2)
V5P0: C3.1 C121.1 C122.1 C123.1 C124.1 C125.1 C126.1 C127.1 C142.1 C159.1 C161.1 D14.1(ANODE) D15.1(ANODE) D16.1(ANODE) D17.1(ANODE) D18.1(ANODE) J20.1 J34.1 J40.1 J143.1 J156.1 R46.1 R310.1 SW9.2 TP9.1 U17.1(IN1) U17.2(IN2) U17.4(BIAS) U17.5(EN) U19.3(IN1) U19.4(IN2) U20.3(IN1) U20.4(IN2) U23.3(IN1) U23.4(IN2) U45.6(VCCB)
V5P0_HDR: J77.113 J77.114 J77.115 J77.116 J156.2
VBAT: BT1.PLUS1(POS1) BT1.PLUS2(POS2) D1.2(ANODE2)
VBUS_HEADER: J53.1 J53.2 SW9.3
VBUS_IN: C47.1 C185.1 J47.1 J53.3 J53.4 L2.2 R190.2 U8.9(OUTA) U37.1(IN)
VDD: C78.1 C79.1 C80.1 C81.1 C82.1 C83.1 C84.1 C85.1 C106.1 C107.1 FB1.1 U1.B10(VDD8) U1.C3(VDD2) U1.E9(VDD4) U1.F11(VDD5) U1.H1(VDD1) U1.J11(VDD7) U1.L5(VDD6) U1.L7(VDD3)
CLKIN: TP15.1(TP) U1.D7(CLKIN)
CLKIN_32: R43.1 U1.D6(CLKIN_32)
CTL0: J1.6 J77.33 R221.2
CTL1: J1.23 J77.51 R222.2
CTL2: J1.25 J77.55 R223.2
CTL3: J1.7 J77.31 R224.2
CTL4: J77.60 J100.1
CTL4_LT: J100.3 U45.3(A)
CTL4_SW: J1.14 J100.2 R225.2
CTL5: J1.13 J77.39 R226.2
CTL6: J1.19 J77.45 R227.2
CTL7: J1.11 J77.37 R228.2
CTL8: J1.21 J77.49 R229.2
CTL9: J1.15 J77.41 R230.2
CTL10: J1.17 J77.43 R231.2
CTL11: J1.16 J77.54 R232.2
CTL12: J1.27 J77.57 R233.2
CVDDQ: C39.1 C112.1 C113.1 J135.3 J135.4 R10.2 R37.2 R38.2 R39.2 R40.1 R63.2 U1.B6(CVDDQ) X2.12(VCC)
DQ0: J1.29 J77.68 R5.2
DQ1: J1.18 J77.74 R205.2
DQ2: J1.20 J77.76 R206.2
DQ3: J1.31 J77.70 R207.2
DQ4: J1.12 J77.50 R208.2
DQ5: J1.28 J77.80 R209.2
DQ6: J1.8 J77.32 R210.2
DQ7: J1.10 J77.42 R211.2
DQ8: J1.24 J77.66 R212.2
DQ9: J1.36 J77.89 R213.2
DQ10: J1.33 J77.61 R214.2
DQ11: J1.30 J77.79 R215.2
DQ12: J1.35 J77.71 R216.2
DQ13: J1.32 J77.81 R217.2
DQ14: J1.37 J77.65 R218.2
DQ15: J1.34 J77.83 R219.2
DQ16: J2.11 J77.56 R6.2
DQ17: J2.27 J77.85 R12.2
DQ18: J2.19 J77.73 R13.2
DQ19: J2.29 J77.87 R14.2
DQ20: J2.23 J77.77 R15.2
DQ21: J2.21 J77.75 R16.2
DQ22: J2.17 J77.69 R17.2
DQ23: J2.25 J77.67 R18.2
DQ24: J2.37 J77.78 R20.2
DQ25: J2.35 J77.72 R21.2
DQ26: J2.15 J77.63 R44.2
DQ27: J2.13 J77.58 R45.2
DQ28: J2.7 J77.38 R49.2
DQ29: J2.31 J77.62 R50.2
DQ30: J2.9 J77.40 R56.2
DQ31: J2.33 J77.64 R57.2
FAULTA_L: R46.2 TP28.1(TP) U8.10(FAULTA_L)
FLAG: R190.1 U37.4(FLAG)
FSLC0: R37.1 R41.2 U1.B2(FSLC0)
FSLC1: R38.1 R42.2 U1.B4(FSLC1)
FSLC2: R39.1 R58.2 U1.E6(FSLC2)
GPIO45: J2.20 TP13.1(TP) U1.F2(GPIO45)
I2C_CHARGER_DETECT: TP31.1(TP) U1.D11(I2C-GPIO60_CHARGER-DETECT)
I2C_SCL_EEPROM: J42.1 J147.2 U44.6(SCL)
I2C_SCL_FX3: J2.34 J42.2 R176.1 U1.D9(I2C-GPIO58_SCL)
I2C_SCL_PPORT: J2.26 J42.3 J77.88
I2C_SDA_EEPROM: J45.1 J147.3 U44.5(SDA)
I2C_SDA_FX3: J2.32 J45.2 R186.1 U1.D10(I2C-GPIO59_SDA)
I2C_SDA_PPORT: J2.24 J45.3 J77.86
I2S-MCLK: J2.6 J20.7 J77.90 R261.2
I2S_CLK: J2.5 J20.4 J77.95 R254.2
I2S_SD: J2.14 J20.5 J77.93 R255.2
I2S_WP: J2.18 J20.6 J77.91 R256.2
INT_N_CTL15: J1.22 J77.52 R170.1 U1.L8(INT_N_CTL15)
N_SRST: J51.15(N_SRST) R51.1
OTG_ID: J48.4(ID) J50.1 U1.C9(OTG_ID)
PCLK: J1.5 J77.44 R220.2
PMODE0_CON: J77.36 J96.1
PMODE1_CON: J77.46 J97.1
PMODE2_CON: J77.30 J98.1
PMODE_0: J96.2 R234.2
PMODE_0_DIP: J96.3 R7.1 SW25.1
PMODE_1: J97.2 R235.2
PMODE_1_DIP: J97.3 R8.1 SW25.2
PMODE_2: J98.2 R236.2
PMODE_2_DIP: J98.3 R19.1 SW25.3
REG_VBATT: D1.1(ANODE1) J74.2 J143.4 J143.5 J143.6
RESET_N: J1.38 J72.2 R10.1 U1.C5(RESET_N)
RESET_N_CON: J72.3 J77.59
RESET_SWITCH: C1.1 J72.1 R63.1 SW8.B1 SW8.B2
RS232_CTS_OUT: J38.7 R27.1
RS232_RTS_IN: J38.8 R33.1
RS232_RX_IN: J38.3 R29.1
RS232_TX_OUT: J38.2 R25.1
RTCK: J51.11(RTCK) J52.2
SPI-MISO_UART-TX: J2.10 J103.2 R259.2
SPI-MOSI_UART-RX: J2.8 J104.2 R260.2
SPI-SCK_UART-RTS: J2.16 J101.2 R257.2
SPI-SSN_UART-CTS: J2.12 J102.2 R258.2
SPI_CLK: J34.3 J101.3 R61.1
SPI_CLK_flash: R61.2 R247.2 U26.6(C)
SPI_Hold#_flash: R248.2 U26.7(~{HOLD})
SPI_MISO: J34.6 J103.3 R60.1
SPI_MISO_flash: R60.2 R246.2 U26.2(Q)
SPI_MOSI: J34.4 J104.3 R59.1
SPI_MOSI_flash: R59.2 R252.2 U26.5(D)
SPI_SSN: J34.5 J102.3 R62.1
SPI_SSN_flash: R62.2 R249.2 U26.1(~{S})
SPI_Wp#_flash: R250.2 R251.2 U26.3(~{W}/VPP)
SS_DM: J48.2(D-) U1.A10(DM)
SS_DP: J48.3(D+) U1.A9(DP)
SS_RX_M: J48.10(MICRO_SSRX+) U1.A3(SSRXM) U9.5 U9.6
SS_RX_P: J48.9(MICRO_SSRX-) U1.A4(SSRXP) U9.4 U9.7
SS_TX_M: C46.2 J48.6(MICRO_SSTX-) U9.1 U9.10
SS_TX_P: C43.2 J48.7(MICRO_SSTX+) U9.2 U9.9
TCK: J51.9(TCK) J52.1 R52.1 U1.F6(TCK)
TDI: J51.5(TDI) R54.1 U1.E7(TDI)
TDO: J51.13(TDO) U1.C10(TDO)
TMS: J51.7(TMS) R53.1 U1.E8(TMS)
TRST_N: J51.3(N_TRST) R55.1 U1.B11(TRST_N)
U3RX_VDDQ: C91.1 C92.1 FB4.1 U1.A2(U3RXVDDQ)
U3TX_VDDQ: C104.1 C105.1 FB5.1 U1.B5(U3TXVDDQ)
UART_CTS: J102.1 U7.3(IO_VL2)
UART_CTS_LT: R26.2 U7.12(IO_VCC2)
UART_FORCE_OFF: R31.1 R35.2 U6.20(FORCEOFF#)
UART_FORCE_ON: R30.1 R34.2 U6.14(FORCEON)
UART_READY: R22.1 R23.2 U6.1(READY)
UART_RTS: J101.1 U7.2(IO_VL1)
UART_RTS_LT: R32.2 U7.13(IO_VCC1)
UART_RX: J104.1 U7.5(IO_VL4)
UART_RX_LT: R28.2 U7.10(IO_VCC4)
UART_TX: J103.1 U7.4(IO_VL3)
UART_TX_LT: R24.2 U7.11(IO_VCC3)
USB3_VBUS: C186.1 U1.E11(VBUS) U37.5(OUT)
USB_DRV_VBUS: R264.1 TP46.1(TP) U8.1(ONA) U45.4(B)
VIO1: C2.1 C86.1 C87.1 C88.1 J125.1 J136.4 J136.5 J136.6 R7.2 R8.2 R11.2 R19.2 R170.2 U1.H11(VIO1_2) U1.L9(VIO1_1) U45.1(VCCA)
VIO1_HDR: J77.1 J77.2 J77.3 J77.4 J77.117 J77.118 J77.119 J77.120 J125.2
VIO2: C108.1 C109.1 J144.4 J144.5 J144.6 U1.F1(VIO2)
VIO3: C110.1 C111.1 J20.2 J145.4 J145.5 J145.6 U1.E3(VIO3)
VIO4: C36.1 C77.1 C114.1 C115.1 J20.3 J34.2 J146.4 J146.5 J146.6 R36.2 R246.1 R248.1 R249.1 R250.1 R252.1 U1.B1(VIO4) U7.1(VL) U26.8(VCC)
VIO5: C89.1 C90.1 C197.1 C212.1 J51.1(VT_REF) J51.2(V_SUPPLY) J134.5 J134.6 J134.7 J134.8 J147.1 R51.2 R52.2 R53.2 R54.2 R55.2 R110.1 R176.2 R186.2 R262.1 R263.1 U1.C11(VIO5) U44.8(VCC)
XTALIN: C216.2 U1.C6(XTALIN) Y3.1
XTALOUT: C217.1 U1.C7(XTALOUT) Y3.3
N13394127: C53.1 D1.3(CATHODE) J74.1 U1.E10(VBAT)
N13841009: R36.1 U7.8(/TS)
N13880067: R29.2 U6.16(R1_IN)
N13882405: R25.2 U6.17(T1_OUT)
N13882880: R27.2 U6.9(R2_IN)
N13883880: R33.2 U6.8(T2_OUT)
N13897864: R32.1 U6.12(T2_IN)
N13897866: R28.1 U6.15(R1_OUT)
N13897868: R26.1 U6.10(R2_OUT)
N13897870: R24.1 U6.13(T1_IN)
N13929197: C33.1 U6.2(C1+)
N13930227: C33.2 U6.4(C1-)
N13931322: C35.1 U6.5(C2+)
N13931334: C35.2 U6.6(C2-)
N13944533: C32.1 U6.3(V+)
N13945074: C34.1 U6.7(V-)
N16663499: R43.2 X2.7(OUT)
N17004628: C42.1 F1.2 U8.2(INA) U8.3(IN) U8.4(INB)
N17006752: F1.1 L1.2
N17006789: J40.2 L1.1
N17020961: C44.1 C45.1 J47.2
N17052408: C43.1 U1.A5(SSTXP)
N17056303: C46.1 U1.A6(SSTXM)
N17073855: C49.1 J48.11(SHIELD1) J48.12(SHIELD2) J48.13(SHIELD3) J48.14(SHIELD4) J48.15(SHIELD5) J48.16(SHIELD6) J48.17(SHIELD7) J48.18(SHIELD8) L5.1
N17441604: R47.1 U1.B3(R_USB3)
N17441606: R48.1 U1.C8(R_USB2)
N17676874: R40.2 X2.1(VIO)
N20153874: J48.1(VBUS) L2.1
N20184217: R5.1 U1.F10(DQ0)
N20186132: R205.1 U1.F9(DQ1)
N20187007: R206.1 U1.F7(DQ2)
N20187884: R207.1 U1.G10(DQ3)
N20188787: R208.1 U1.G9(DQ4)
N20188789: R209.1 U1.F8(DQ5)
N20188799: R210.1 U1.H10(DQ6)
N20188809: R211.1 U1.H9(DQ7)
N20189728: R212.1 U1.J10(DQ8)
N20189730: R213.1 U1.J9(DQ9)
N20189740: R214.1 U1.K11(DQ10)
N20189750: R215.1 U1.L10(DQ11)
N20190677: R216.1 U1.K10(DQ12)
N20190679: R217.1 U1.K9(DQ13)
N20190689: R218.1 U1.J8(DQ14)
N20190699: R219.1 U1.G8(DQ15)
N20191634: R220.1 U1.J6(PCLK)
N20191636: R221.1 U1.K8(CTL0)
N20191646: R222.1 U1.K7(CTL1)
N20191656: R223.1 U1.J7(CTL2)
N20192599: R224.1 U1.H7(CTL3)
N20192601: R225.1 U1.G7(CTL4)
N20192611: R226.1 U1.G6(CTL5)
N20192621: R227.1 U1.K6(CTL6)
N20193572: R228.1 U1.H8(CTL7)
N20193574: R229.1 U1.G5(CTL8)
N20193584: R230.1 U1.H6(CTL9)
N20193594: R231.1 U1.K5(CTL10)
N20194553: R232.1 U1.J5(CTL11)
N20195482: R233.1 U1.H5(CTL12)
N20198119: R234.1 U1.G4(PMODE0)
N20199051: R235.1 U1.H4(PMODE1)
N20199985: R236.1 U1.L4(PMODE2)
N21712030: Q13.3(C) R301.1
N21712032: Q13.1(B) R300.2
N21712149: D14.2(CATHODE) R301.2
N21712617: Q14.3(C) R302.1
N21712619: Q14.1(B) R306.2
N21712675: D18.2(CATHODE) R302.2
N21838652: R254.1 U1.D1(I2S-CLK)
N21838662: R255.1 U1.D2(I2S-SD)
N21838672: R256.1 U1.D3(I2S-WS)
N21838834: R261.1 U1.C4(I2S-MCLK)
N21839162: R257.1 U1.D4(UART-RTS_SPI-SCK)
N21839172: R258.1 U1.C1(UART-CTS_SPI-SSN)
N21839182: R259.1 U1.C2(UART-TX_SPI-MISO)
N21839192: R260.1 U1.D5(UART-RX_SPI-MOSI)
N21886398: R11.1 U45.5(OE)
N21902204: R6.1 U1.K2(DQ16)
N21902237: R12.1 U1.J4(DQ17)
N21902264: R13.1 U1.K1(DQ18)
N21902291: R14.1 U1.J2(DQ19)
N21902318: R15.1 U1.J3(DQ20)
N21902345: R16.1 U1.J1(DQ21)
N21902372: R17.1 U1.H2(DQ22)
N21902399: R18.1 U1.H3(DQ23)
N21902426: R20.1 U1.F4(DQ24)
N21902453: R21.1 U1.G2(DQ25)
N21902480: R44.1 U1.G3(DQ26)
N21902507: R45.1 U1.F3(DQ27)
N21902708: R49.1 U1.F5(DQ28)
N21902721: R50.1 U1.E1(DQ29)
N21902734: R56.1 U1.E5(DQ30)
N21902747: R57.1 U1.E4(DQ31)
N21904014: R237.1 U17.3(PG)
N21904020: R238.2 R239.1 U17.8(FB)
N21904073: C129.1 U17.7(SS)
N21905805: R141.1 R144.2 U19.7(FB)
N21905847: R139.1 U19.8(PG)
N21905950: R240.2 R242.2 U20.7(FB)
N21905997: R241.1 U20.8(PG)
N21906513: R243.2 R245.2 U23.7(FB)
N21906562: R244.1 U23.8(PG)
N21921971: R110.2 SW40.6 U44.3(A2)
N21921973: R263.2 SW40.7 U44.2(A1)
N21921975: R262.2 SW40.8 U44.1(A0)
N21922075: R111.1 U44.7(WP)
N22050803: Q15.3(C) R307.1
N22050805: Q15.1(B) R308.2
N22050813: D15.2(CATHODE) R307.2
N22050947: Q16.3(C) R309.1
N22050949: Q16.1(B) R310.2
N22050957: D16.2(CATHODE) R309.2
N22051184: Q17.3(C) R311.1
N22051186: Q17.1(B) R312.2
N22051194: D17.2(CATHODE) R311.2

Not connected (* = marked no-connect by the designer): J1 1* 2* 4* 9* 26*; J2 1* 2* 4* 22* 28* 30* 36* 38*; J38 1* 4* 6* 9*; J51 17(DBGRQ)* 19(DBGACK)*; J77 5* 6* 7* 8* 9* 10* 11* 12* 13* 14* 15* 16* 17* 18* 19* 20* 21* 22* 23* 24* 25* 26* 27* 28* 29* 34* 35* 47* 48* 53* 82* 84* 92* 94* 96* 97* 98* 99* 100* 101* 102* 103* 104* 105* 106* 107* 108* 109* 110* 111* 112*; SW25 4* 5*; SW40 4* 5*; U1 A11(NC)*; U7 6(NC1)* 9(NC2)*; U8 5(ONB)* 6(FAULTB_L)* 7(OUTB)*; X2 2(NC1)* 3(NC2)* 4(NC3)* 5(NC4)* 8(NC5)* 9(NC6)* 10(NC7)* 11(NC8)*

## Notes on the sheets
sheet 1
- FSLC [0..2]
- CLOCK SIGNALS
- DNL
- DNL
- DNL
- CRYSTAL
- CLOCK IN_32
sheet 2
- POWER LED
sheet 3
- FX3 POWER & DECOUPLING
- GND LOOP TEST POINTS
sheet 4
- FX3 DVK DEVICE BOARD
- REV - 3.0
- PAGE 01 : INDEX PAGE
  PAGE 02 : P-PORT CONNECTIONS 1
  PAGE 03 : P/S0/S1 PORT TO SAMTEC
  PAGE 04 : MICTOR CONNECTIONS
  PAGE 05 : S0/S1 PORT CONNECTIONS
  PAGE 06 : S1 TO  UART/I2C EEPROM
  PAGE 07 : CLOCK SIGNALS
  PAGE 08 : JTAG CONNECTIONS
  PAGE 09 : USB CONNECTIONS
  PAGE 10 : FX3 POWER
  PAGE 11 : 5V INPUT / 3.3V - 2.5V REG
  PAGE 12 : 1.2V / 1.8V REG
  PAGE 13 : POWER CONNECTORS
  PAGE 14 : POWER LED'S
- PCB NUMBER :
- 600-60015-01 REV03
- FAB DRAWING NUMBER :
- 610-60012-01 REV03
- ASSEMBLY DRAWING NUMBER :
- 620-60013-01 REV03
- SCHEMATIC NUMBER :
- 630-60013-01 REV03
sheet 5
- MICTOR CONNECTIONS
- P-PORT SIGNALS
- S0/S1-PORT SIGNALS
sheet 6
- USB SWITCH
- USB CONNECTIONS
- 0 = OTG DEVICE
- 1 = HOST
- USB3.0  MICRO -TYPE B
- 0 = NORMAL
- USB Positive Overvoltage
- 1 = ID GND
- Protection Controller
- ESD DEVICE
sheet 7
- VIO1
- VIO2
- VIO3
- VIO4
- VIO5
- VDD,SRAM_VDD,EFVDDQ
- CVDDQ
- REG_VBATT
- AVDD
- U3TX_VDDQ
- U3RX_VDDQ
sheet 8
- JTAG CONNECTIONS
sheet 9
- P PORT  TO SAMTEC
sheet 10
- P-PORT CONNECTIONS
- RESET_CONNECTION
sheet 11
- S1 UART CONNECTIONS
- LEVEL TRANSLATOR
- I2C EEPROM
sheet 12
- I2S HEADER
- SPI HEADER
- S0-PORT CONNECTIONS
- SAMTEC
- OPTION
- SPI FLASH RES OPTION
- Place close to Flash U26
- S1-PORT CONNECTIONS
- SPI Flash
- FLASH VCC : 2.3-3.6V
- LVDDQ     : 1.8/2.5V/3.3V
sheet 13
- 5V - DC INPUT POWER
- 5V DC INPUT
- 2.5V @ 1A REGULATOR
- 3.3V  @ 1.5A  REGULATOR
- (R2)
sheet 14
- 1.2V @ 1A REGULATOR
- (R2)
- 1.8V @ 1A REGULATOR
- (R2)
